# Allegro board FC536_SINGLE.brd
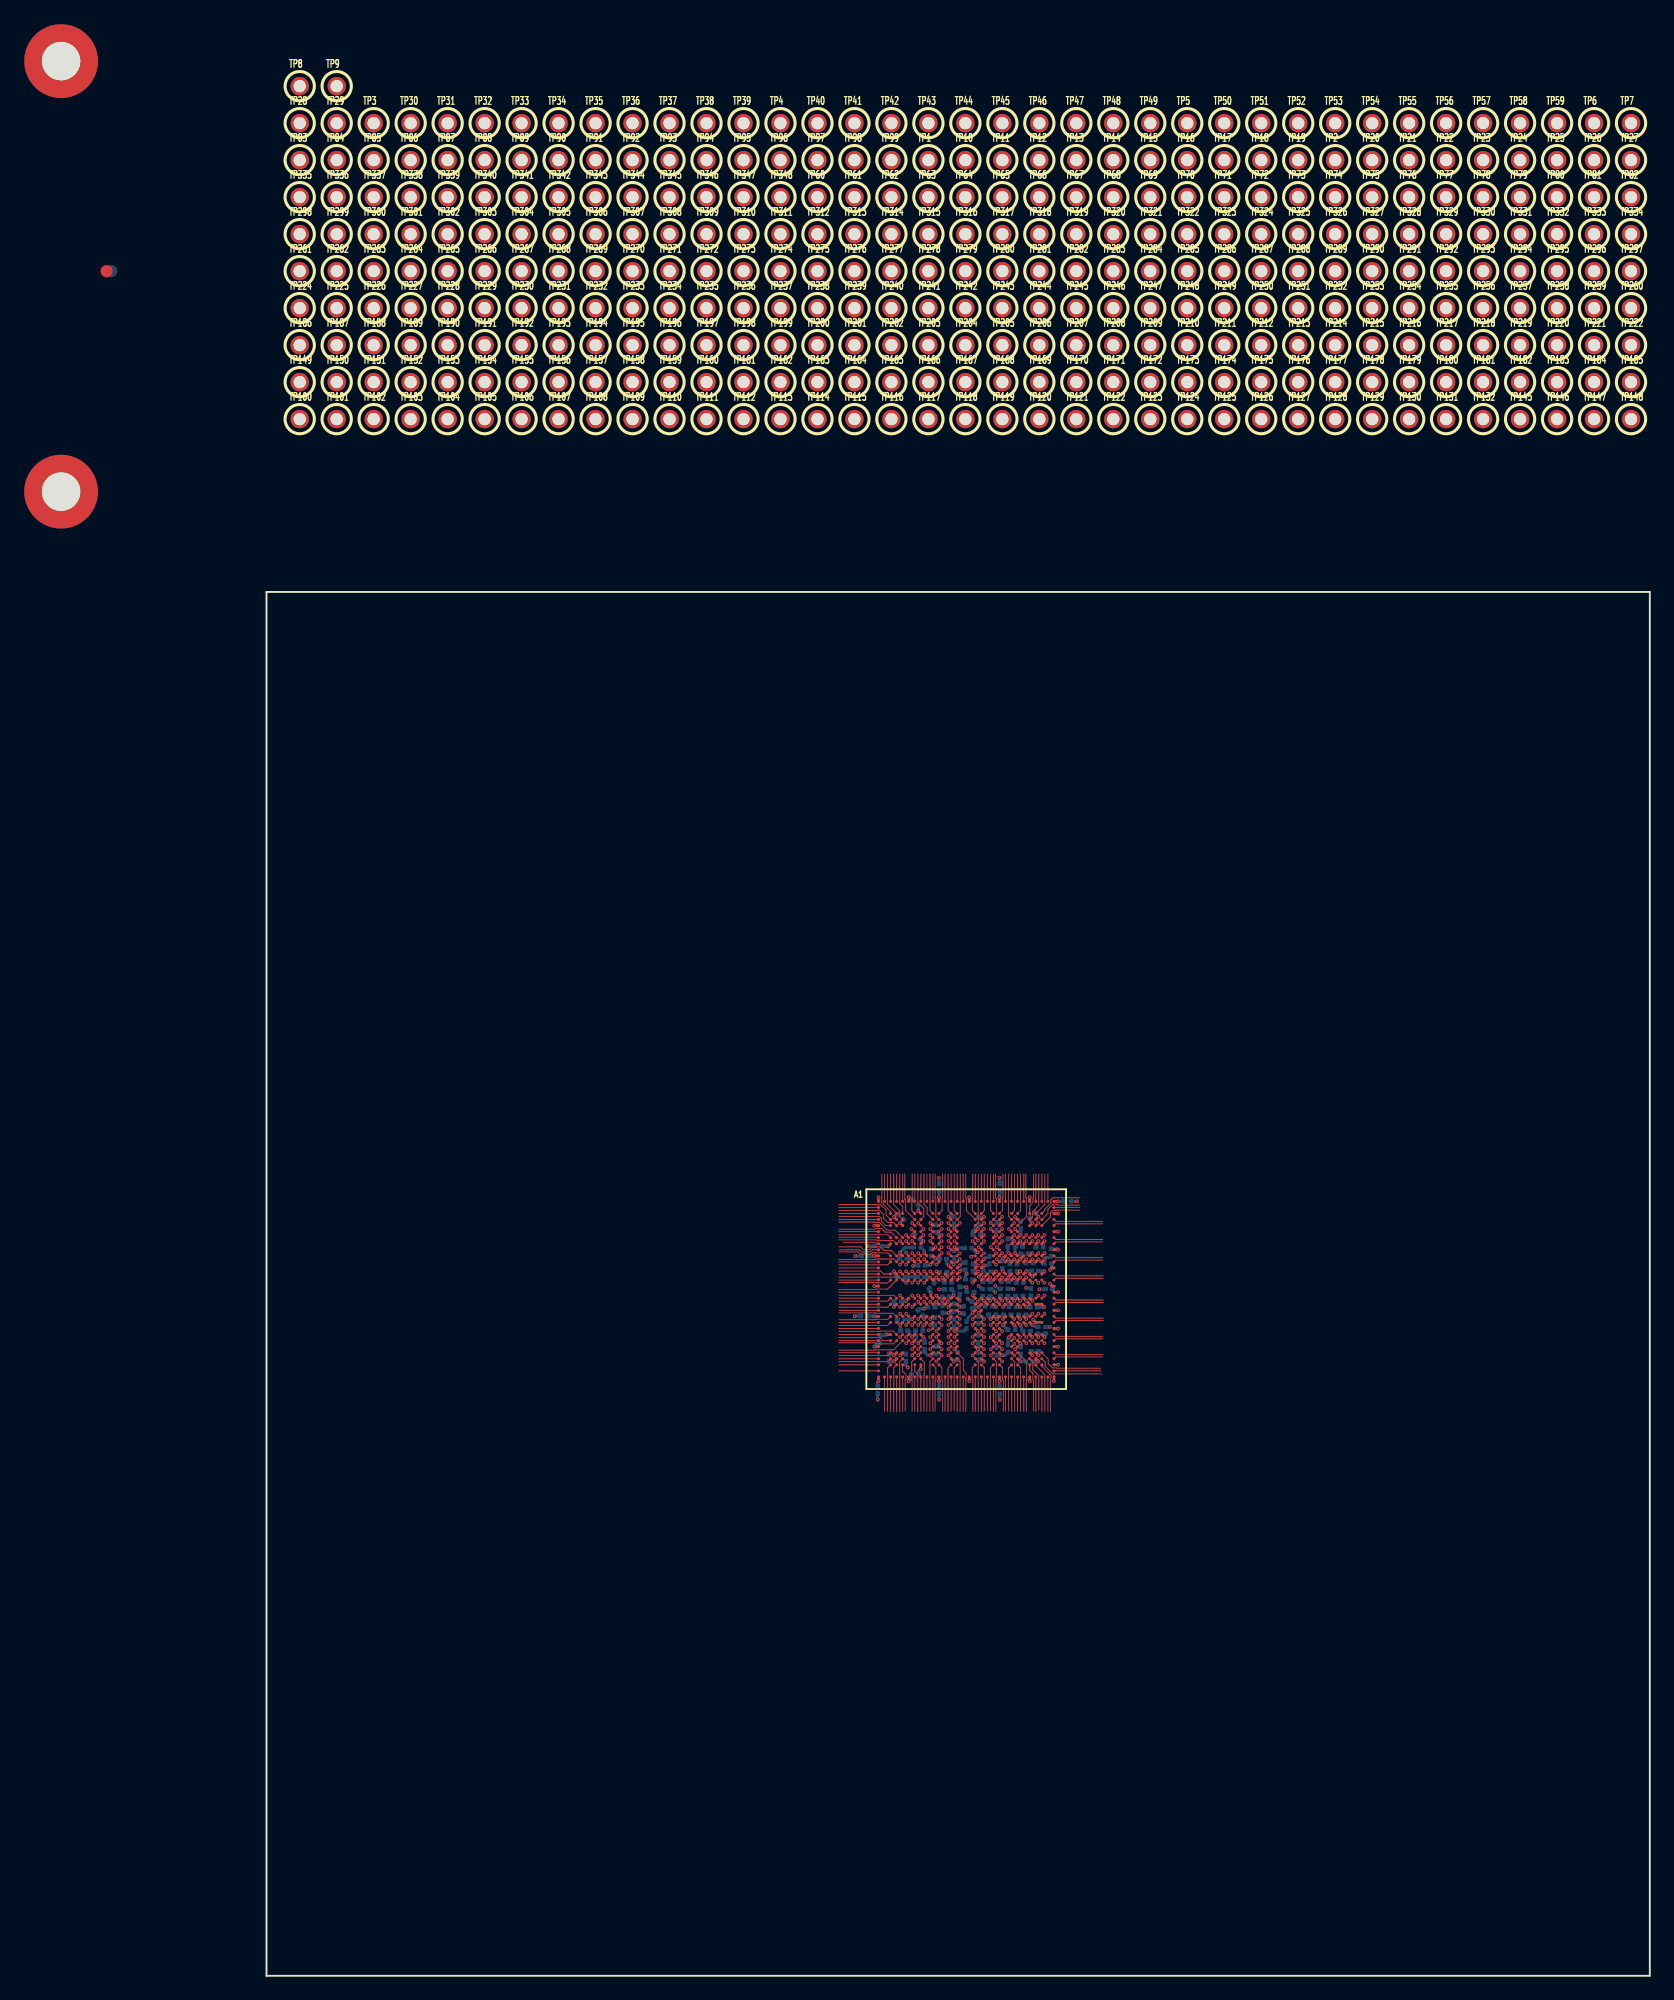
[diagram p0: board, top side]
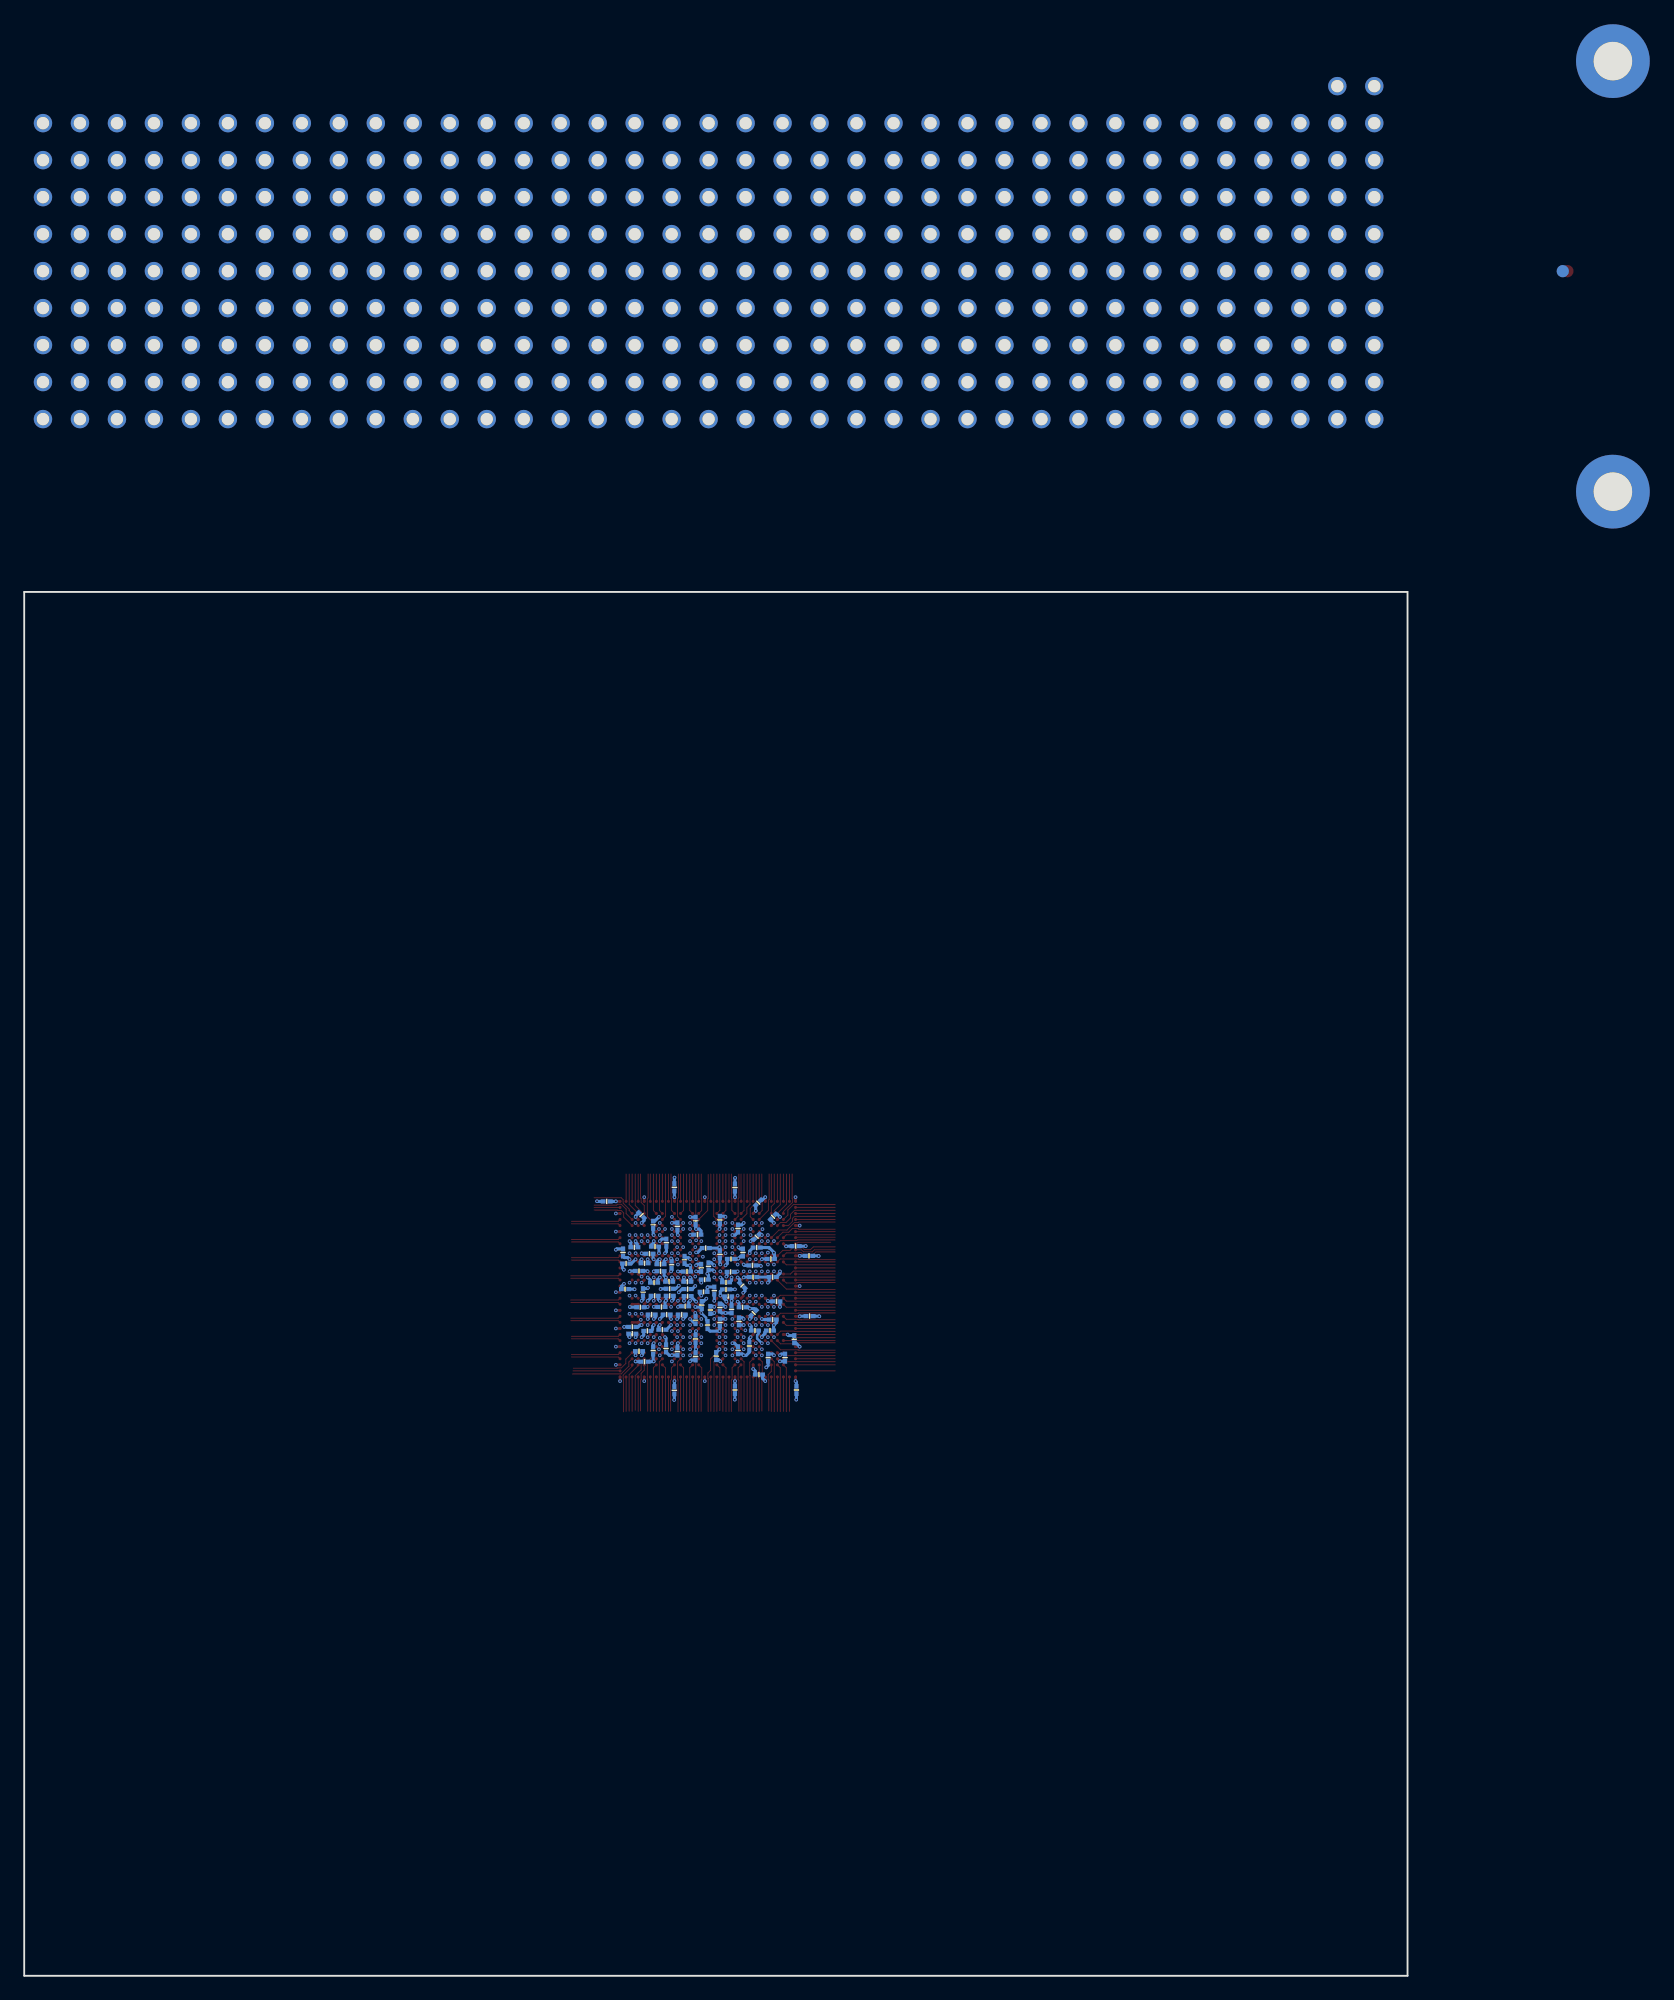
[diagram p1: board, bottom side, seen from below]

Outline 114.3 x 114.3 mm; copper layers: TOP, L2_GND, SIG1, SIG2, L3_PWR, BOTTOM. Coordinates in mm from the lower left corner of the outline.
Outline path: 0,114.3 114.3,114.3 114.3,0 0,0 0,114.3

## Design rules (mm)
net group SERDES_0_INT_REFCLK_: nets SERDES_0_INT_REFCLK_N SERDES_0_INT_REFCLK_P
net group SERDES_0_RX0_: nets SERDES_0_RX0_N SERDES_0_RX0_P
net group SERDES_0_RX1_: nets SERDES_0_RX1_N SERDES_0_RX1_P
net group SERDES_0_RX2_: nets SERDES_0_RX2_N SERDES_0_RX2_P
net group SERDES_0_RX3_: nets SERDES_0_RX3_N SERDES_0_RX3_P
net group SERDES_0_TX0_: nets SERDES_0_TX0_N SERDES_0_TX0_P
net group SERDES_0_TX1_: nets SERDES_0_TX1_N SERDES_0_TX1_P
net group SERDES_0_TX2_: nets SERDES_0_TX2_N SERDES_0_TX2_P
net group SERDES_0_TX3_: nets SERDES_0_TX3_N SERDES_0_TX3_P
net group SERDES_0N_EXT_REFCLK_: nets SERDES_0N_EXT_REFCLK_N SERDES_0N_EXT_REFCLK_P
net group SERDES_0S_EXT_REFCLK_: nets SERDES_0S_EXT_REFCLK_N SERDES_0S_EXT_REFCLK_P

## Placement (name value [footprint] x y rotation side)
C1  0.1UF/10V  [BGA_0201]  56.13 56.11 180 bottom
C2  0.1UF/10V  [BGA_0201]  56.31 56.69 180 bottom
C3  0.1UF/10V  [BGA_0201]  61.01 57.33 180 bottom
C4  0.1UF/10V  [BGA_0201]  58.17 56.49 0 bottom
C5  0.1UF/10V  [BGA_0201]  59.51 57.33 0 bottom
C6  0.1UF/10V  [BGA_0201]  60.96 56.16 180 bottom
C7  0.1UF/10V  [BGA_0201]  59.69 55.3 0 bottom
C8  0.1UF/10V  [BGA_0201]  59.49 56.72 0 bottom
C9  0.1UF/10V  [BGA_0201]  59.49 56.13 0 bottom
C10  0.1UF/10V  [BGA_0201]  57.84 53.75 90 bottom
C11  0.1UF/10V  [BGA_0201]  55.85 55.04 90 bottom
C12  0.1UF/10V  [BGA_0201]  54.94 55.22 0 bottom
C13  0.1UF/10V  [BGA_0201]  56.31 57.28 180 bottom
C14  0.1UF/10V  [BGA_0201]  60.96 56.74 180 bottom
C15  0.1UF/10V  [BGA_0201]  60.81 58.72 270 bottom
C16  0.1UF/10V  [BGA_0201]  58.32 55.4 270 bottom
C17  0.1UF/10V  [BGA_0201]  59.54 58.17 0 bottom
C18  0.1UF/10V  [BGA_0201]  56.82 55.19 90 bottom
C19  0.1UF/10V  [BGA_0201]  61.21 54.61 180 bottom
C20  0.1UF/10V  [BGA_0201]  58.83 54.15 270 bottom
C21  0.1UF/10V  [BGA_0201]  51.44 51.05 90 bottom
C22  0.1UF/10V  [BGA_0201]  54.03 54.74 315 bottom
C23  0.1UF/10V  [BGA_0201]  57.61 54.99 270 bottom
C24  0.1UF/10V  [BGA_0201]  63.5 51.59 0 bottom
C25  0.1UF/10V  [BGA_0201]  59.97 54.61 180 bottom
C26  0.1UF/10V  [BGA_0201]  61.24 60.55 90 bottom
C27  0.1UF/10V  [BGA_0201]  54.91 59.74 90 bottom
C28  0.1UF/10V  [BGA_0201]  57.28 56.59 270 bottom
C29  0.1UF/10V  [BGA_0201]  58.06 57.51 0 bottom
C30  0.1UF/10V  [BGA_0201]  61.26 51.82 90 bottom
C31  0.1UF/10V  [BGA_0201]  54.38 52.02 90 bottom
C32  0.1UF/10V  [BGA_0201]  63.04 58.85 180 bottom
C33  0.1UF/10V  [BGA_0201]  62.46 54.61 0 bottom
C34  0.1UF/10V  [BGA_0201]  62.64 59.64 0 bottom
C35  0.1UF/10V  [BGA_0201]  63.88 60.17 180 bottom
C36  0.1UF/10V  [BGA_0201]  64.06 53.59 180 bottom
C37  0.1UF/10V  [BGA_0201]  63.17 56.46 270 bottom
C38  0.1UF/10V  [BGA_0201]  61.72 58.19 0 bottom
C39  0.1UF/10V  [BGA_0201]  61.65 55.24 0 bottom
C40  0.1UF/10V  [BGA_0201]  64.65 56.72 180 bottom
C41  0.1UF/10V  [BGA_0201]  64.06 53.04 180 bottom
C42  0.1UF/10V  [BGA_0201]  62.81 53.26 180 bottom
C43  0.1UF/10V  [BGA_0201]  62.2 56.16 180 bottom
C44  0.1UF/10V  [BGA_0201]  62.26 57.25 180 bottom
C45  0.1UF/10V  [BGA_0201]  62.18 60.22 180 bottom
C46  0.1UF/10V  [BGA_0201]  58.67 61.21 0 bottom
C47  0.1UF/10V  [BGA_0201]  53.78 61.04 315 bottom
C48  0.1UF/10V  [BGA_0201]  57.76 58.6 90 bottom
C49  0.1UF/10V  [BGA_0201]  56.82 59.59 270 bottom
C50  0.1UF/10V  [BGA_0201]  59.74 59.13 90 bottom
C51  0.1UF/10V  [BGA_0201]  58.37 58.47 90 bottom
C52  0.1UF/10V  [BGA_0201]  54.97 57.01 225 bottom
C53  0.1UF/10V  [BGA_0201]  53.77 60.15 0 bottom
C54  0.1UF/10V  [BGA_0201]  53.92 53.29 0 bottom
C55  0.1UF/10V  [BGA_0201]  55.93 58.14 180 bottom
C56  0.1UF/10V  [BGA_0201]  50.5 48.39 270 bottom
C57  0.1UF/10V  [BGA_0201]  55.58 48.39 270 bottom
C58  0.1UF/10V  [BGA_0201]  52.83 51.05 270 bottom
C59  0.1UF/10V  [BGA_0201]  56.82 53.95 270 bottom
C60  0.1UF/10V  [BGA_0201]  53.59 49.66 180 bottom
C61  0.1UF/10V  [BGA_0201]  55.32 51.66 270 bottom
C62  0.1UF/10V  [BGA_0201]  57.12 51.18 270 bottom
C63  0.1UF/10V  [BGA_0201]  52.68 53.29 180 bottom
C64  0.1UF/10V  [BGA_0201]  55.24 54.05 270 bottom
C65  0.1UF/10V  [BGA_0201]  62.33 51.64 270 bottom
C66  0.1UF/10V  [BGA_0201]  63.04 50.72 180 bottom
C67  0.1UF/10V  [BGA_0201]  60.33 51.56 270 bottom
C68  0.1UF/10V  [BGA_0201]  58.83 52.6 270 bottom
C69  0.1UF/10V  [BGA_0201]  58.83 51.16 90 bottom
C70  0.1UF/10V  [BGA_0201]  60.58 48.36 270 bottom
C71  0.1UF/10V  [BGA_0201]  61.57 53.37 0 bottom
C72  0.1UF/10V  [BGA_0201]  61.72 58.78 0 bottom
C73  0.1UF/10V  [BGA_0201]  58.83 62.36 270 bottom
C74  0.1UF/10V  [BGA_0201]  56.82 62.43 90 bottom
C75  0.1UF/10V  [BGA_0201]  55.32 61.72 90 bottom
C76  0.1UF/10V  [BGA_0201]  66.17 63.96 0 bottom
C77  0.1UF/10V  [BGA_0201]  53.64 63.86 135 bottom
C78  0.1UF/10V  [BGA_0201]  60.58 65.13 90 bottom
C79  0.1UF/10V  [BGA_0201]  55.58 65.1 90 bottom
C80  0.1UF/10V  [BGA_0201]  63.3 62.81 225 bottom
C81  0.1UF/10V  [BGA_0201]  57.99 60.11 180 bottom
C82  0.1UF/10V  [BGA_0201]  60.33 61.9 90 bottom
C83  0.1UF/10V  [BGA_0201]  62.33 62.03 90 bottom
C84  0.1UF/10V  [BGA_0201]  54.13 58.67 180 bottom
C85  0.1UF/10V  [BGA_0201]  55.91 59.21 180 bottom
C86  0.1UF/10V  [BGA_0201]  50.67 52.58 270 bottom
C87  0.1UF/10V  [BGA_0201]  49.4 54.48 180 bottom
C88  0.1UF/10V  [BGA_0201]  52.15 55.7 180 bottom
C89  0.1UF/10V  [BGA_0201]  54.08 57.71 180 bottom
C90  0.1UF/10V  [BGA_0201]  52.45 54.2 180 bottom
C91  0.1UF/10V  [BGA_0201]  52.45 57.71 0 bottom
C92  0.1UF/10V  [BGA_0201]  49.45 59.46 180 bottom
C93  0.1UF/10V  [BGA_0201]  50.56 60.26 180 bottom
C94  0.1UF/10V  [BGA_0201]  52.43 62.69 135 bottom
C95  0.1UF/10V  [BGA_0201]  52.6 59.21 180 bottom
C96  0.1UF/10V  [BGA_0201]  63.5 58.22 0 bottom
C97  0.1UF/10V  [BGA_0201]  63.4 55.22 0 bottom
C98  0.1UF/10V  [BGA_0201]  64.82 59.74 90 bottom
C99  0.1UF/10V  [BGA_0201]  64.57 58.83 0 bottom
NOREF  -  [unnamed]  -16.97 158.14 0 top
NOREF#2  -  [unnamed]  -13.21 140.79 0 top
NOREF#3  -  [#2]  306.73 11.62 0 top
NOREF#4  -  [unnamed]  -16.97 122.58 0 top
NOREF#5  -  [unnamed]  -12.83 140.79 180 bottom
TP1  TP  [TP_40D60]  54.69 149.96 0 top
TP2  TP  [TP_40D60]  88.3 149.96 0 top
TP3  TP  [TP_40D60]  8.86 153.02 0 top
TP4  TP  [TP_40D60]  42.47 153.02 0 top
TP5  TP  [TP_40D60]  76.08 153.02 0 top
TP6  TP  [TP_40D60]  109.69 153.02 0 top
TP7  TP  [TP_40D60]  112.75 153.02 0 top
TP8  TP  [TP_40D60]  2.75 156.07 0 top
TP9  TP  [TP_40D60]  5.8 156.07 0 top
TP10  TP  [TP_40D60]  57.75 149.96 0 top
TP11  TP  [TP_40D60]  60.8 149.96 0 top
TP12  TP  [TP_40D60]  63.86 149.96 0 top
TP13  TP  [TP_40D60]  66.92 149.96 0 top
TP14  TP  [TP_40D60]  69.97 149.96 0 top
TP15  TP  [TP_40D60]  73.03 149.96 0 top
TP16  TP  [TP_40D60]  76.08 149.96 0 top
TP17  TP  [TP_40D60]  79.14 149.96 0 top
TP18  TP  [TP_40D60]  82.19 149.96 0 top
TP19  TP  [TP_40D60]  85.25 149.96 0 top
TP20  TP  [TP_40D60]  91.36 149.96 0 top
TP21  TP  [TP_40D60]  94.42 149.96 0 top
TP22  TP  [TP_40D60]  97.47 149.96 0 top
TP23  TP  [TP_40D60]  100.53 149.96 0 top
TP24  TP  [TP_40D60]  103.58 149.96 0 top
TP25  TP  [TP_40D60]  106.64 149.96 0 top
TP26  TP  [TP_40D60]  109.69 149.96 0 top
TP27  TP  [TP_40D60]  112.75 149.96 0 top
TP28  TP  [TP_40D60]  2.75 153.02 0 top
TP29  TP  [TP_40D60]  5.8 153.02 0 top
TP30  TP  [TP_40D60]  11.91 153.02 0 top
TP31  TP  [TP_40D60]  14.97 153.02 0 top
TP32  TP  [TP_40D60]  18.03 153.02 0 top
TP33  TP  [TP_40D60]  21.08 153.02 0 top
TP34  TP  [TP_40D60]  24.14 153.02 0 top
TP35  TP  [TP_40D60]  27.19 153.02 0 top
TP36  TP  [TP_40D60]  30.25 153.02 0 top
TP37  TP  [TP_40D60]  33.3 153.02 0 top
TP38  TP  [TP_40D60]  36.36 153.02 0 top
TP39  TP  [TP_40D60]  39.41 153.02 0 top
TP40  TP  [TP_40D60]  45.53 153.02 0 top
TP41  TP  [TP_40D60]  48.58 153.02 0 top
TP42  TP  [TP_40D60]  51.64 153.02 0 top
TP43  TP  [TP_40D60]  54.69 153.02 0 top
TP44  TP  [TP_40D60]  57.75 153.02 0 top
TP45  TP  [TP_40D60]  60.8 153.02 0 top
TP46  TP  [TP_40D60]  63.86 153.02 0 top
TP47  TP  [TP_40D60]  66.92 153.02 0 top
TP48  TP  [TP_40D60]  69.97 153.02 0 top
TP49  TP  [TP_40D60]  73.03 153.02 0 top
TP50  TP  [TP_40D60]  79.14 153.02 0 top
TP51  TP  [TP_40D60]  82.19 153.02 0 top
TP52  TP  [TP_40D60]  85.25 153.02 0 top
TP53  TP  [TP_40D60]  88.3 153.02 0 top
TP54  TP  [TP_40D60]  91.36 153.02 0 top
TP55  TP  [TP_40D60]  94.42 153.02 0 top
TP56  TP  [TP_40D60]  97.47 153.02 0 top
TP57  TP  [TP_40D60]  100.53 153.02 0 top
TP58  TP  [TP_40D60]  103.58 153.02 0 top
TP59  TP  [TP_40D60]  106.64 153.02 0 top
TP60  TP  [TP_40D60]  45.53 146.91 0 top
TP61  TP  [TP_40D60]  48.58 146.91 0 top
TP62  TP  [TP_40D60]  51.64 146.91 0 top
TP63  TP  [TP_40D60]  54.69 146.91 0 top
TP64  TP  [TP_40D60]  57.75 146.91 0 top
TP65  TP  [TP_40D60]  60.8 146.91 0 top
TP66  TP  [TP_40D60]  63.86 146.91 0 top
TP67  TP  [TP_40D60]  66.92 146.91 0 top
TP68  TP  [TP_40D60]  69.97 146.91 0 top
TP69  TP  [TP_40D60]  73.03 146.91 0 top
TP70  TP  [TP_40D60]  76.08 146.91 0 top
TP71  TP  [TP_40D60]  79.14 146.91 0 top
TP72  TP  [TP_40D60]  82.19 146.91 0 top
TP73  TP  [TP_40D60]  85.25 146.91 0 top
TP74  TP  [TP_40D60]  88.3 146.91 0 top
TP75  TP  [TP_40D60]  91.36 146.91 0 top
TP76  TP  [TP_40D60]  94.42 146.91 0 top
TP77  TP  [TP_40D60]  97.47 146.91 0 top
TP78  TP  [TP_40D60]  100.53 146.91 0 top
TP79  TP  [TP_40D60]  103.58 146.91 0 top
TP80  TP  [TP_40D60]  106.64 146.91 0 top
TP81  TP  [TP_40D60]  109.69 146.91 0 top
TP82  TP  [TP_40D60]  112.75 146.91 0 top
TP83  TP  [TP_40D60]  2.75 149.96 0 top
TP84  TP  [TP_40D60]  5.8 149.96 0 top
TP85  TP  [TP_40D60]  8.86 149.96 0 top
TP86  TP  [TP_40D60]  11.91 149.96 0 top
TP87  TP  [TP_40D60]  14.97 149.96 0 top
TP88  TP  [TP_40D60]  18.03 149.96 0 top
TP89  TP  [TP_40D60]  21.08 149.96 0 top
TP90  TP  [TP_40D60]  24.14 149.96 0 top
TP91  TP  [TP_40D60]  27.19 149.96 0 top
TP92  TP  [TP_40D60]  30.25 149.96 0 top
TP93  TP  [TP_40D60]  33.3 149.96 0 top
TP94  TP  [TP_40D60]  36.36 149.96 0 top
TP95  TP  [TP_40D60]  39.41 149.96 0 top
TP96  TP  [TP_40D60]  42.47 149.96 0 top
TP97  TP  [TP_40D60]  45.53 149.96 0 top
TP98  TP  [TP_40D60]  48.58 149.96 0 top
TP99  TP  [TP_40D60]  51.64 149.96 0 top
TP100  TP  [TP_40D60]  2.75 128.57 0 top
TP101  TP  [TP_40D60]  5.8 128.57 0 top
TP102  TP  [TP_40D60]  8.86 128.57 0 top
TP103  TP  [TP_40D60]  11.91 128.57 0 top
TP104  TP  [TP_40D60]  14.97 128.57 0 top
TP105  TP  [TP_40D60]  18.03 128.57 0 top
TP106  TP  [TP_40D60]  21.08 128.57 0 top
TP107  TP  [TP_40D60]  24.14 128.57 0 top
TP108  TP  [TP_40D60]  27.19 128.57 0 top
TP109  TP  [TP_40D60]  30.25 128.57 0 top
TP110  TP  [TP_40D60]  33.3 128.57 0 top
TP111  TP  [TP_40D60]  36.36 128.57 0 top
TP112  TP  [TP_40D60]  39.41 128.57 0 top
TP113  TP  [TP_40D60]  42.47 128.57 0 top
TP114  TP  [TP_40D60]  45.53 128.57 0 top
TP115  TP  [TP_40D60]  48.58 128.57 0 top
TP116  TP  [TP_40D60]  51.64 128.57 0 top
TP117  TP  [TP_40D60]  54.69 128.57 0 top
TP118  TP  [TP_40D60]  57.75 128.57 0 top
TP119  TP  [TP_40D60]  60.8 128.57 0 top
TP120  TP  [TP_40D60]  63.86 128.57 0 top
TP121  TP  [TP_40D60]  66.92 128.57 0 top
TP122  TP  [TP_40D60]  69.97 128.57 0 top
TP123  TP  [TP_40D60]  73.03 128.57 0 top
TP124  TP  [TP_40D60]  76.08 128.57 0 top
TP125  TP  [TP_40D60]  79.14 128.57 0 top
TP126  TP  [TP_40D60]  82.19 128.57 0 top
TP127  TP  [TP_40D60]  85.25 128.57 0 top
TP128  TP  [TP_40D60]  88.3 128.57 0 top
TP129  TP  [TP_40D60]  91.36 128.57 0 top
TP130  TP  [TP_40D60]  94.42 128.57 0 top
TP131  TP  [TP_40D60]  97.47 128.57 0 top
TP132  TP  [TP_40D60]  100.53 128.57 0 top
TP145  TP  [TP_40D60]  103.58 128.57 0 top
TP146  TP  [TP_40D60]  106.64 128.57 0 top
TP147  TP  [TP_40D60]  109.69 128.57 0 top
TP148  TP  [TP_40D60]  112.75 128.57 0 top
TP149  TP  [TP_40D60]  2.75 131.63 0 top
TP150  TP  [TP_40D60]  5.8 131.63 0 top
TP151  TP  [TP_40D60]  8.86 131.63 0 top
TP152  TP  [TP_40D60]  11.91 131.63 0 top
TP153  TP  [TP_40D60]  14.97 131.63 0 top
TP154  TP  [TP_40D60]  18.03 131.63 0 top
TP155  TP  [TP_40D60]  21.08 131.63 0 top
TP156  TP  [TP_40D60]  24.14 131.63 0 top
TP157  TP  [TP_40D60]  27.19 131.63 0 top
TP158  TP  [TP_40D60]  30.25 131.63 0 top
TP159  TP  [TP_40D60]  33.3 131.63 0 top
TP160  TP  [TP_40D60]  36.36 131.63 0 top
TP161  TP  [TP_40D60]  39.41 131.63 0 top
TP162  TP  [TP_40D60]  42.47 131.63 0 top
TP163  TP  [TP_40D60]  45.53 131.63 0 top
TP164  TP  [TP_40D60]  48.58 131.63 0 top
TP165  TP  [TP_40D60]  51.64 131.63 0 top
TP166  TP  [TP_40D60]  54.69 131.63 0 top
TP167  TP  [TP_40D60]  57.75 131.63 0 top
TP168  TP  [TP_40D60]  60.8 131.63 0 top
TP169  TP  [TP_40D60]  63.86 131.63 0 top
TP170  TP  [TP_40D60]  66.92 131.63 0 top
TP171  TP  [TP_40D60]  69.97 131.63 0 top
TP172  TP  [TP_40D60]  73.03 131.63 0 top
TP173  TP  [TP_40D60]  76.08 131.63 0 top
TP174  TP  [TP_40D60]  79.14 131.63 0 top
TP175  TP  [TP_40D60]  82.19 131.63 0 top
TP176  TP  [TP_40D60]  85.25 131.63 0 top
TP177  TP  [TP_40D60]  88.3 131.63 0 top
TP178  TP  [TP_40D60]  91.36 131.63 0 top
TP179  TP  [TP_40D60]  94.42 131.63 0 top
TP180  TP  [TP_40D60]  97.47 131.63 0 top
TP181  TP  [TP_40D60]  100.53 131.63 0 top
TP182  TP  [TP_40D60]  103.58 131.63 0 top
TP183  TP  [TP_40D60]  106.64 131.63 0 top
TP184  TP  [TP_40D60]  109.69 131.63 0 top
TP185  TP  [TP_40D60]  112.75 131.63 0 top
TP186  TP  [TP_40D60]  2.75 134.68 0 top
TP187  TP  [TP_40D60]  5.8 134.68 0 top
TP188  TP  [TP_40D60]  8.86 134.68 0 top
TP189  TP  [TP_40D60]  11.91 134.68 0 top
TP190  TP  [TP_40D60]  14.97 134.68 0 top
TP191  TP  [TP_40D60]  18.03 134.68 0 top
TP192  TP  [TP_40D60]  21.08 134.68 0 top
TP193  TP  [TP_40D60]  24.14 134.68 0 top
TP194  TP  [TP_40D60]  27.19 134.68 0 top
TP195  TP  [TP_40D60]  30.25 134.68 0 top
TP196  TP  [TP_40D60]  33.3 134.68 0 top
TP197  TP  [TP_40D60]  36.36 134.68 0 top
TP198  TP  [TP_40D60]  39.41 134.68 0 top
TP199  TP  [TP_40D60]  42.47 134.68 0 top
TP200  TP  [TP_40D60]  45.53 134.68 0 top
TP201  TP  [TP_40D60]  48.58 134.68 0 top
TP202  TP  [TP_40D60]  51.64 134.68 0 top
TP203  TP  [TP_40D60]  54.69 134.68 0 top
TP204  TP  [TP_40D60]  57.75 134.68 0 top
TP205  TP  [TP_40D60]  60.8 134.68 0 top
TP206  TP  [TP_40D60]  63.86 134.68 0 top
TP207  TP  [TP_40D60]  66.92 134.68 0 top
TP208  TP  [TP_40D60]  69.97 134.68 0 top
TP209  TP  [TP_40D60]  73.03 134.68 0 top
TP210  TP  [TP_40D60]  76.08 134.68 0 top
TP211  TP  [TP_40D60]  79.14 134.68 0 top
TP212  TP  [TP_40D60]  82.19 134.68 0 top
TP213  TP  [TP_40D60]  85.25 134.68 0 top
TP214  TP  [TP_40D60]  88.3 134.68 0 top
TP215  TP  [TP_40D60]  91.36 134.68 0 top
TP216  TP  [TP_40D60]  94.42 134.68 0 top
TP217  TP  [TP_40D60]  97.47 134.68 0 top
TP218  TP  [TP_40D60]  100.53 134.68 0 top
TP219  TP  [TP_40D60]  103.58 134.68 0 top
TP220  TP  [TP_40D60]  106.64 134.68 0 top
TP221  TP  [TP_40D60]  109.69 134.68 0 top
TP222  TP  [TP_40D60]  112.75 134.68 0 top
TP224  TP  [TP_40D60]  2.75 137.74 0 top
TP225  TP  [TP_40D60]  5.8 137.74 0 top
TP226  TP  [TP_40D60]  8.86 137.74 0 top
TP227  TP  [TP_40D60]  11.91 137.74 0 top
TP228  TP  [TP_40D60]  14.97 137.74 0 top
TP229  TP  [TP_40D60]  18.03 137.74 0 top
TP230  TP  [TP_40D60]  21.08 137.74 0 top
TP231  TP  [TP_40D60]  24.14 137.74 0 top
TP232  TP  [TP_40D60]  27.19 137.74 0 top
TP233  TP  [TP_40D60]  30.25 137.74 0 top
TP234  TP  [TP_40D60]  33.3 137.74 0 top
TP235  TP  [TP_40D60]  36.36 137.74 0 top
TP236  TP  [TP_40D60]  39.41 137.74 0 top
TP237  TP  [TP_40D60]  42.47 137.74 0 top
TP238  TP  [TP_40D60]  45.53 137.74 0 top
TP239  TP  [TP_40D60]  48.58 137.74 0 top
TP240  TP  [TP_40D60]  51.64 137.74 0 top
TP241  TP  [TP_40D60]  54.69 137.74 0 top
TP242  TP  [TP_40D60]  57.75 137.74 0 top
TP243  TP  [TP_40D60]  60.8 137.74 0 top
TP244  TP  [TP_40D60]  63.86 137.74 0 top
TP245  TP  [TP_40D60]  66.92 137.74 0 top
TP246  TP  [TP_40D60]  69.97 137.74 0 top
TP247  TP  [TP_40D60]  73.03 137.74 0 top
TP248  TP  [TP_40D60]  76.08 137.74 0 top
TP249  TP  [TP_40D60]  79.14 137.74 0 top
TP250  TP  [TP_40D60]  82.19 137.74 0 top
TP251  TP  [TP_40D60]  85.25 137.74 0 top
TP252  TP  [TP_40D60]  88.3 137.74 0 top
TP253  TP  [TP_40D60]  91.36 137.74 0 top
TP254  TP  [TP_40D60]  94.42 137.74 0 top
TP255  TP  [TP_40D60]  97.47 137.74 0 top
TP256  TP  [TP_40D60]  100.53 137.74 0 top
TP257  TP  [TP_40D60]  103.58 137.74 0 top
TP258  TP  [TP_40D60]  106.64 137.74 0 top
TP259  TP  [TP_40D60]  109.69 137.74 0 top
TP260  TP  [TP_40D60]  112.75 137.74 0 top
TP261  TP  [TP_40D60]  2.75 140.8 0 top
TP262  TP  [TP_40D60]  5.8 140.8 0 top
TP263  TP  [TP_40D60]  8.86 140.8 0 top
TP264  TP  [TP_40D60]  11.91 140.8 0 top
TP265  TP  [TP_40D60]  14.97 140.8 0 top
TP266  TP  [TP_40D60]  18.03 140.8 0 top
TP267  TP  [TP_40D60]  21.08 140.8 0 top
TP268  TP  [TP_40D60]  24.14 140.8 0 top
TP269  TP  [TP_40D60]  27.19 140.8 0 top
TP270  TP  [TP_40D60]  30.25 140.8 0 top
TP271  TP  [TP_40D60]  33.3 140.8 0 top
TP272  TP  [TP_40D60]  36.36 140.8 0 top
TP273  TP  [TP_40D60]  39.41 140.8 0 top
TP274  TP  [TP_40D60]  42.47 140.8 0 top
TP275  TP  [TP_40D60]  45.53 140.8 0 top
TP276  TP  [TP_40D60]  48.58 140.8 0 top
TP277  TP  [TP_40D60]  51.64 140.8 0 top
TP278  TP  [TP_40D60]  54.69 140.8 0 top
TP279  TP  [TP_40D60]  57.75 140.8 0 top
TP280  TP  [TP_40D60]  60.8 140.8 0 top
TP281  TP  [TP_40D60]  63.86 140.8 0 top
TP282  TP  [TP_40D60]  66.92 140.8 0 top
TP283  TP  [TP_40D60]  69.97 140.8 0 top
TP284  TP  [TP_40D60]  73.03 140.8 0 top
TP285  TP  [TP_40D60]  76.08 140.8 0 top
TP286  TP  [TP_40D60]  79.14 140.8 0 top
TP287  TP  [TP_40D60]  82.19 140.8 0 top
TP288  TP  [TP_40D60]  85.25 140.8 0 top
TP289  TP  [TP_40D60]  88.3 140.8 0 top
TP290  TP  [TP_40D60]  91.36 140.8 0 top
TP291  TP  [TP_40D60]  94.42 140.8 0 top
TP292  TP  [TP_40D60]  97.47 140.8 0 top
TP293  TP  [TP_40D60]  100.53 140.8 0 top
TP294  TP  [TP_40D60]  103.58 140.8 0 top
TP295  TP  [TP_40D60]  106.64 140.8 0 top
TP296  TP  [TP_40D60]  109.69 140.8 0 top
TP297  TP  [TP_40D60]  112.75 140.8 0 top
TP298  TP  [TP_40D60]  2.75 143.85 0 top
TP299  TP  [TP_40D60]  5.8 143.85 0 top
TP300  TP  [TP_40D60]  8.86 143.85 0 top
TP301  TP  [TP_40D60]  11.91 143.85 0 top
TP302  TP  [TP_40D60]  14.97 143.85 0 top
TP303  TP  [TP_40D60]  18.03 143.85 0 top
TP304  TP  [TP_40D60]  21.08 143.85 0 top
TP305  TP  [TP_40D60]  24.14 143.85 0 top
TP306  TP  [TP_40D60]  27.19 143.85 0 top
TP307  TP  [TP_40D60]  30.25 143.85 0 top
TP308  TP  [TP_40D60]  33.3 143.85 0 top
TP309  TP  [TP_40D60]  36.36 143.85 0 top
TP310  TP  [TP_40D60]  39.41 143.85 0 top
TP311  TP  [TP_40D60]  42.47 143.85 0 top
TP312  TP  [TP_40D60]  45.53 143.85 0 top
TP313  TP  [TP_40D60]  48.58 143.85 0 top
TP314  TP  [TP_40D60]  51.64 143.85 0 top
TP315  TP  [TP_40D60]  54.69 143.85 0 top
TP316  TP  [TP_40D60]  57.75 143.85 0 top
TP317  TP  [TP_40D60]  60.8 143.85 0 top
TP318  TP  [TP_40D60]  63.86 143.85 0 top
TP319  TP  [TP_40D60]  66.92 143.85 0 top
TP320  TP  [TP_40D60]  69.97 143.85 0 top
TP321  TP  [TP_40D60]  73.03 143.85 0 top
TP322  TP  [TP_40D60]  76.08 143.85 0 top
TP323  TP  [TP_40D60]  79.14 143.85 0 top
TP324  TP  [TP_40D60]  82.19 143.85 0 top
TP325  TP  [TP_40D60]  85.25 143.85 0 top
TP326  TP  [TP_40D60]  88.3 143.85 0 top
TP327  TP  [TP_40D60]  91.36 143.85 0 top
TP328  TP  [TP_40D60]  94.42 143.85 0 top
TP329  TP  [TP_40D60]  97.47 143.85 0 top
TP330  TP  [TP_40D60]  100.53 143.85 0 top
TP331  TP  [TP_40D60]  103.58 143.85 0 top
TP332  TP  [TP_40D60]  106.64 143.85 0 top
TP333  TP  [TP_40D60]  109.69 143.85 0 top
TP334  TP  [TP_40D60]  112.75 143.85 0 top
TP335  TP  [TP_40D60]  2.75 146.91 0 top
TP336  TP  [TP_40D60]  5.8 146.91 0 top
TP337  TP  [TP_40D60]  8.86 146.91 0 top
TP338  TP  [TP_40D60]  11.91 146.91 0 top
TP339  TP  [TP_40D60]  14.97 146.91 0 top
TP340  TP  [TP_40D60]  18.03 146.91 0 top
TP341  TP  [TP_40D60]  21.08 146.91 0 top
TP342  TP  [TP_40D60]  24.14 146.91 0 top
TP343  TP  [TP_40D60]  27.19 146.91 0 top
TP344  TP  [TP_40D60]  30.25 146.91 0 top
TP345  TP  [TP_40D60]  33.3 146.91 0 top
TP346  TP  [TP_40D60]  36.36 146.91 0 top
TP347  TP  [TP_40D60]  39.41 146.91 0 top
TP348  TP  [TP_40D60]  42.47 146.91 0 top
U1  -  [M5P300-FCS536]  57.82 56.71 0 top

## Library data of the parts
C1-C99 = CAPACITOR NON-POL
TP1-TP132 TP145-TP222 TP224-TP348 = T POINT A
U1 = M5P300-FCS536_Pin

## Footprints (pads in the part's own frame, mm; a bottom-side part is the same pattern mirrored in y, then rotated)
BGA_0201
  rect 0.4x0.35 smd: 1(-0.3,0) 2(0.3,0)
M5P300-FCS536
  round 0.254 smd: A1(-7.25,7.25) A2(-6.75,7.25) A3(-6.25,7.25) A4(-5.75,7.25) A5(-5.25,7.25) A6(-4.75,7.25) A7(-4.25,7.25) A8(-3.75,7.25) A9(-3.25,7.25) A10(-2.75,7.25) A11(-2.25,7.25) A12(-1.75,7.25) A13(-1.25,7.25) A14(-0.75,7.25) A15(-0.25,7.25) A16(0.25,7.25) A17(0.75,7.25) A18(1.25,7.25) A19(1.75,7.25) A20(2.25,7.25) A21(2.75,7.25) A22(3.25,7.25) A23(3.75,7.25) A24(4.25,7.25) A25(4.75,7.25) A26(5.25,7.25) A27(5.75,7.25) A28(6.25,7.25) A29(6.75,7.25) A30(7.25,7.25) AA1(-7.25,-2.75) AA3(-6.25,-2.75) AA4(-5.75,-2.75) AA5(-5.25,-2.75) AA6(-4.75,-2.75) AA7(-4.25,-2.75) AA8(-3.75,-2.75) AA9(-3.25,-2.75) AA10(-2.75,-2.75) AA11(-2.25,-2.75) AA13(-1.25,-2.75) AA14(-0.75,-2.75) AA17(0.75,-2.75) AA18(1.25,-2.75) AA20(2.25,-2.75) AA21(2.75,-2.75) AA22(3.25,-2.75) AA23(3.75,-2.75) AA24(4.25,-2.75) AA25(4.75,-2.75) AA26(5.25,-2.75) AA27(5.75,-2.75) AA28(6.25,-2.75) AA30(7.25,-2.75) AB1(-7.25,-3.25) AB10(-2.75,-3.25) AB11(-2.25,-3.25) AB13(-1.25,-3.25) AB14(-0.75,-3.25) AB17(0.75,-3.25) AB18(1.25,-3.25) AB20(2.25,-3.25) AB21(2.75,-3.25) AB30(7.25,-3.25) AC1(-7.25,-3.75) AC3(-6.25,-3.75) AC4(-5.75,-3.75) AC5(-5.25,-3.75) AC6(-4.75,-3.75) AC7(-4.25,-3.75) AC8(-3.75,-3.75) AC10(-2.75,-3.75) AC11(-2.25,-3.75) AC13(-1.25,-3.75) AC14(-0.75,-3.75) AC17(0.75,-3.75) AC18(1.25,-3.75) AC20(2.25,-3.75) AC21(2.75,-3.75) AC23(3.75,-3.75) AC24(4.25,-3.75) AC25(4.75,-3.75) AC26(5.25,-3.75) AC27(5.75,-3.75) AC28(6.25,-3.75) AC30(7.25,-3.75) AD1(-7.25,-4.25) AD3(-6.25,-4.25) AD4(-5.75,-4.25) AD5(-5.25,-4.25) AD6(-4.75,-4.25) AD7(-4.25,-4.25) AD8(-3.75,-4.25) AD10(-2.75,-4.25) AD11(-2.25,-4.25) AD13(-1.25,-4.25) AD14(-0.75,-4.25) AD17(0.75,-4.25) AD18(1.25,-4.25) AD20(2.25,-4.25) AD21(2.75,-4.25) AD23(3.75,-4.25) AD24(4.25,-4.25) AD25(4.75,-4.25) AD26(5.25,-4.25) AD27(5.75,-4.25) AD28(6.25,-4.25) AD30(7.25,-4.25) AE1(-7.25,-4.75) AE7(-4.25,-4.75) AE8(-3.75,-4.75) AE10(-2.75,-4.75) AE11(-2.25,-4.75) AE13(-1.25,-4.75) AE14(-0.75,-4.75) AE17(0.75,-4.75) AE18(1.25,-4.75) AE20(2.25,-4.75) AE21(2.75,-4.75) AE23(3.75,-4.75) AE24(4.25,-4.75) AE30(7.25,-4.75) AF1(-7.25,-5.25) AF3(-6.25,-5.25) AF4(-5.75,-5.25) AF5(-5.25,-5.25) AF7(-4.25,-5.25) AF8(-3.75,-5.25) AF10(-2.75,-5.25) AF11(-2.25,-5.25) AF13(-1.25,-5.25) AF14(-0.75,-5.25) AF17(0.75,-5.25) AF18(1.25,-5.25) AF20(2.25,-5.25) AF21(2.75,-5.25) AF23(3.75,-5.25) AF24(4.25,-5.25) AF26(5.25,-5.25) AF27(5.75,-5.25) AF28(6.25,-5.25) AF30(7.25,-5.25) AG1(-7.25,-5.75) AG3(-6.25,-5.75) AG4(-5.75,-5.75) AG5(-5.25,-5.75) AG7(-4.25,-5.75) AG8(-3.75,-5.75) AG10(-2.75,-5.75) AG11(-2.25,-5.75) AG13(-1.25,-5.75) AG14(-0.75,-5.75) AG17(0.75,-5.75) AG18(1.25,-5.75) AG20(2.25,-5.75) AG21(2.75,-5.75) AG23(3.75,-5.75) AG24(4.25,-5.75) AG26(5.25,-5.75) AG27(5.75,-5.75) AG28(6.25,-5.75) AG30(7.25,-5.75) AH1(-7.25,-6.25) AH3(-6.25,-6.25) AH4(-5.75,-6.25) AH5(-5.25,-6.25) AH7(-4.25,-6.25) AH8(-3.75,-6.25) AH10(-2.75,-6.25) AH11(-2.25,-6.25) AH13(-1.25,-6.25) AH14(-0.75,-6.25) AH17(0.75,-6.25) AH18(1.25,-6.25) AH20(2.25,-6.25) AH21(2.75,-6.25) AH23(3.75,-6.25) AH24(4.25,-6.25) AH26(5.25,-6.25) AH27(5.75,-6.25) AH28(6.25,-6.25) AH30(7.25,-6.25) AJ1(-7.25,-6.75) AJ30(7.25,-6.75) AK1(-7.25,-7.25) AK2(-6.75,-7.25) AK3(-6.25,-7.25) AK4(-5.75,-7.25) AK5(-5.25,-7.25) AK6(-4.75,-7.25) AK7(-4.25,-7.25) AK8(-3.75,-7.25) AK9(-3.25,-7.25) AK10(-2.75,-7.25) AK11(-2.25,-7.25) AK12(-1.75,-7.25) AK13(-1.25,-7.25) AK14(-0.75,-7.25) AK15(-0.25,-7.25) AK16(0.25,-7.25) AK17(0.75,-7.25) AK18(1.25,-7.25) AK19(1.75,-7.25) AK20(2.25,-7.25) AK21(2.75,-7.25) AK22(3.25,-7.25) AK23(3.75,-7.25) AK24(4.25,-7.25) AK25(4.75,-7.25) AK26(5.25,-7.25) AK27(5.75,-7.25) AK28(6.25,-7.25) AK29(6.75,-7.25) AK30(7.25,-7.25) B1(-7.25,6.75) B30(7.25,6.75) C1(-7.25,6.25) C3(-6.25,6.25) C4(-5.75,6.25) C5(-5.25,6.25) C7(-4.25,6.25) C8(-3.75,6.25) C10(-2.75,6.25) C11(-2.25,6.25) C13(-1.25,6.25) C14(-0.75,6.25) C17(0.75,6.25) C18(1.25,6.25) C20(2.25,6.25) C21(2.75,6.25) C23(3.75,6.25) C24(4.25,6.25) C26(5.25,6.25) C27(5.75,6.25) C28(6.25,6.25) C30(7.25,6.25) D1(-7.25,5.75) D3(-6.25,5.75) D4(-5.75,5.75) D5(-5.25,5.75) D7(-4.25,5.75) D8(-3.75,5.75) D10(-2.75,5.75) D11(-2.25,5.75) D13(-1.25,5.75) D14(-0.75,5.75) D17(0.75,5.75) D18(1.25,5.75) D20(2.25,5.75) D21(2.75,5.75) D23(3.75,5.75) D24(4.25,5.75) D26(5.25,5.75) D27(5.75,5.75) D28(6.25,5.75) D30(7.25,5.75) E1(-7.25,5.25) E3(-6.25,5.25) E4(-5.75,5.25) E5(-5.25,5.25) E7(-4.25,5.25) E8(-3.75,5.25) E10(-2.75,5.25) E11(-2.25,5.25) E13(-1.25,5.25) E14(-0.75,5.25) E17(0.75,5.25) E18(1.25,5.25) E20(2.25,5.25) E21(2.75,5.25) E23(3.75,5.25) E24(4.25,5.25) E26(5.25,5.25) E27(5.75,5.25) E28(6.25,5.25) E30(7.25,5.25) F1(-7.25,4.75) F7(-4.25,4.75) F8(-3.75,4.75) F10(-2.75,4.75) F11(-2.25,4.75) F13(-1.25,4.75) F14(-0.75,4.75) F17(0.75,4.75) F18(1.25,4.75) F20(2.25,4.75) F21(2.75,4.75) F23(3.75,4.75) F24(4.25,4.75) F30(7.25,4.75) G1(-7.25,4.25) G3(-6.25,4.25) G4(-5.75,4.25) G5(-5.25,4.25) G6(-4.75,4.25) G7(-4.25,4.25) G8(-3.75,4.25) G10(-2.75,4.25) G11(-2.25,4.25) G13(-1.25,4.25) G14(-0.75,4.25) G17(0.75,4.25) G18(1.25,4.25) G20(2.25,4.25) G21(2.75,4.25) G23(3.75,4.25) G24(4.25,4.25) G25(4.75,4.25) G26(5.25,4.25) G27(5.75,4.25) G28(6.25,4.25) G30(7.25,4.25) H1(-7.25,3.75) H3(-6.25,3.75) H4(-5.75,3.75) H5(-5.25,3.75) H6(-4.75,3.75) H7(-4.25,3.75) H8(-3.75,3.75) H10(-2.75,3.75) H11(-2.25,3.75) H13(-1.25,3.75) H14(-0.75,3.75) H17(0.75,3.75) H18(1.25,3.75) H20(2.25,3.75) H21(2.75,3.75) H23(3.75,3.75) H24(4.25,3.75) H25(4.75,3.75) H26(5.25,3.75) H27(5.75,3.75) H28(6.25,3.75) H30(7.25,3.75) J1(-7.25,3.25) J10(-2.75,3.25) J11(-2.25,3.25) J13(-1.25,3.25) J14(-0.75,3.25) J17(0.75,3.25) J18(1.25,3.25) J20(2.25,3.25) J21(2.75,3.25) J30(7.25,3.25) K1(-7.25,2.75) K3(-6.25,2.75) K4(-5.75,2.75) K5(-5.25,2.75) K6(-4.75,2.75) K7(-4.25,2.75) K8(-3.75,2.75) K9(-3.25,2.75) K10(-2.75,2.75) K11(-2.25,2.75) K13(-1.25,2.75) K14(-0.75,2.75) K17(0.75,2.75) K18(1.25,2.75) K20(2.25,2.75) K21(2.75,2.75) K22(3.25,2.75) K23(3.75,2.75) K24(4.25,2.75) K25(4.75,2.75) K26(5.25,2.75) K27(5.75,2.75) K28(6.25,2.75) K30(7.25,2.75) L1(-7.25,2.25) L3(-6.25,2.25) L4(-5.75,2.25) L5(-5.25,2.25) L6(-4.75,2.25) L7(-4.25,2.25) L8(-3.75,2.25) L9(-3.25,2.25) L10(-2.75,2.25) L11(-2.25,2.25) L13(-1.25,2.25) L14(-0.75,2.25) L17(0.75,2.25) L18(1.25,2.25) L20(2.25,2.25) L21(2.75,2.25) L22(3.25,2.25) L23(3.75,2.25) L24(4.25,2.25) L25(4.75,2.25) L26(5.25,2.25) L27(5.75,2.25) L28(6.25,2.25) L30(7.25,2.25) M1(-7.25,1.75) M13(-1.25,1.75) M14(-0.75,1.75) M17(0.75,1.75) M18(1.25,1.75) M30(7.25,1.75) N1(-7.25,1.25) N3(-6.25,1.25) N4(-5.75,1.25) N5(-5.25,1.25) N6(-4.75,1.25) N7(-4.25,1.25) N8(-3.75,1.25) N9(-3.25,1.25) N10(-2.75,1.25) N11(-2.25,1.25) N12(-1.75,1.25) N13(-1.25,1.25) N14(-0.75,1.25) N17(0.75,1.25) N18(1.25,1.25) N19(1.75,1.25) N20(2.25,1.25) N21(2.75,1.25) N22(3.25,1.25) N23(3.75,1.25) N24(4.25,1.25) N25(4.75,1.25) N26(5.25,1.25) N27(5.75,1.25) N28(6.25,1.25) N30(7.25,1.25) P1(-7.25,0.75) P3(-6.25,0.75) P4(-5.75,0.75) P5(-5.25,0.75) P6(-4.75,0.75) P7(-4.25,0.75) P8(-3.75,0.75) P9(-3.25,0.75) P10(-2.75,0.75) P11(-2.25,0.75) P12(-1.75,0.75) P13(-1.25,0.75) P14(-0.75,0.75) P17(0.75,0.75) P18(1.25,0.75) P19(1.75,0.75) P20(2.25,0.75) P21(2.75,0.75) P22(3.25,0.75) P23(3.75,0.75) P24(4.25,0.75) P25(4.75,0.75) P26(5.25,0.75) P27(5.75,0.75) P28(6.25,0.75) P30(7.25,0.75) R1(-7.25,0.25) R30(7.25,0.25) T1(-7.25,-0.25) T30(7.25,-0.25) U1(-7.25,-0.75) U3(-6.25,-0.75) U4(-5.75,-0.75) U5(-5.25,-0.75) U6(-4.75,-0.75) U7(-4.25,-0.75) U8(-3.75,-0.75) U9(-3.25,-0.75) U10(-2.75,-0.75) U11(-2.25,-0.75) U12(-1.75,-0.75) U13(-1.25,-0.75) U14(-0.75,-0.75) U17(0.75,-0.75) U18(1.25,-0.75) U19(1.75,-0.75) U20(2.25,-0.75) U21(2.75,-0.75) U22(3.25,-0.75) U23(3.75,-0.75) U24(4.25,-0.75) U25(4.75,-0.75) U26(5.25,-0.75) U27(5.75,-0.75) U28(6.25,-0.75) U30(7.25,-0.75) V1(-7.25,-1.25) V3(-6.25,-1.25) V4(-5.75,-1.25) V5(-5.25,-1.25) V6(-4.75,-1.25) V7(-4.25,-1.25) V8(-3.75,-1.25) V9(-3.25,-1.25) V10(-2.75,-1.25) V11(-2.25,-1.25) V12(-1.75,-1.25) V13(-1.25,-1.25) V14(-0.75,-1.25) V17(0.75,-1.25) V18(1.25,-1.25) V19(1.75,-1.25) V20(2.25,-1.25) V21(2.75,-1.25) V22(3.25,-1.25) V23(3.75,-1.25) V24(4.25,-1.25) V25(4.75,-1.25) V26(5.25,-1.25) V27(5.75,-1.25) V28(6.25,-1.25) V30(7.25,-1.25) W1(-7.25,-1.75) W13(-1.25,-1.75) W14(-0.75,-1.75) W17(0.75,-1.75) W18(1.25,-1.75) W30(7.25,-1.75) Y1(-7.25,-2.25) Y3(-6.25,-2.25) Y4(-5.75,-2.25) Y5(-5.25,-2.25) Y6(-4.75,-2.25) Y7(-4.25,-2.25) Y8(-3.75,-2.25) Y9(-3.25,-2.25) Y10(-2.75,-2.25) Y11(-2.25,-2.25) Y13(-1.25,-2.25) Y14(-0.75,-2.25) Y17(0.75,-2.25) Y18(1.25,-2.25) Y20(2.25,-2.25) Y21(2.75,-2.25) Y22(3.25,-2.25) Y23(3.75,-2.25) Y24(4.25,-2.25) Y25(4.75,-2.25) Y26(5.25,-2.25) Y27(5.75,-2.25) Y28(6.25,-2.25) Y30(7.25,-2.25)
TP_40D60
  round 1.524 hole 1.016: 1(0,0)
unnamed
  round 6.096 hole 3.175 unplated: (0,0)

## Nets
GND: C1.1 C2.1 C3.1 C4.1 C5.1 C6.1 C7.1 C8.1 C9.1 C10.1 C11.1 C12.1 C13.1 C14.1 C15.1 C16.1 C17.1 C18.1 C19.1 C20.1 C21.1 C22.1 C23.1 C24.1 C25.1 C26.1 C27.1 C28.1 C29.1 C30.1 C31.1 C32.1 C33.1 C34.1 C35.1 C36.1 C37.1 C38.1 C39.1 C40.1 C41.1 C42.1 C43.1 C44.1 C45.1 C46.1 C47.1 C48.1 C49.1 C50.1 C51.1 C52.1 C53.1 C54.1 C55.1 C56.2 C57.2 C58.2 C59.2 C60.2 C61.2 C62.2 C63.2 C64.2 C65.2 C66.2 C67.2 C68.2 C69.2 C70.2 C71.2 C72.2 C73.2 C74.2 C75.2 C76.2 C77.2 C78.2 C79.2 C80.2 C81.2 C82.2 C83.2 C84.2 C85.2 C86.2 C87.2 C88.2 C89.2 C90.2 C91.2 C92.2 C93.2 C94.2 C95.2 C96.2 C97.2 C98.2 C99.2 U1.A1(VSS_1) U1.A6(VSS_4) U1.A16(VSS_2) U1.A26(VSS_3) U1.AA5(VSS_6) U1.AA10(VSS_5) U1.AA23(VSSA_1) U1.AA25(VSSA_2) U1.AA27(VSSA_3) U1.AA28(VSSA_4) U1.AB14(VSS_7) U1.AB30(VSSA_5) U1.AC24(VSS_8) U1.AC26(VSSA_6) U1.AC28(VSSA_7) U1.AD7(VSS_9) U1.AE1(VSS_10) U1.AE17(VSS_11) U1.AE30(VSSA_8) U1.AF10(VSS_12) U1.AF21(VSS_13) U1.AF26(VSS_14) U1.AG4(VSS_17) U1.AG13(VSS_15) U1.AG24(VSS_16) U1.AH30(VSSA_9) U1.AK6(VSS_21) U1.AK16(VSS_18) U1.AK26(VSS_19) U1.AK30(VSS_20) U1.C30(VSSA_10) U1.D4(VSS_24) U1.D13(VSS_22) U1.D24(VSS_23) U1.E1(VSS_25) U1.E10(VSS_26) U1.E21(VSS_27) U1.E26(VSS_28) U1.F17(VSS_29) U1.F30(VSSA_11) U1.G7(VSS_30) U1.H24(VSS_31) U1.H26(VSSA_12) U1.H28(VSSA_13) U1.J14(VSS_32) U1.J30(VSSA_14) U1.K5(VSS_35) U1.K10(VSS_33) U1.K22(VSS_34) U1.K23(VSSA_15) U1.K25(VSSA_16) U1.K27(VSSA_17) U1.K28(VSSA_18) U1.L23(VSSA_19) U1.L24(VSSA_20) U1.L26(VSSA_21) U1.M18(VSS_36) U1.M30(VSSA_22) U1.N12(VSS_37) U1.N14(VSS_38) U1.N17(VSS_39) U1.N19(VSS_40) U1.N21(VSS_41) U1.N23(VSSA_23) U1.N26(VSSA_24) U1.N27(VSSA_25) U1.N28(VSSA_26) U1.P6(VSS_47) U1.P11(VSS_42) U1.P13(VSS_43) U1.P18(VSS_44) U1.P20(VSS_45) U1.P22(VSS_46) U1.P24(VSSA_27) U1.P25(VSSA_28) U1.R1(VSS_48) U1.R30(VSSA_29) U1.T30(VSSA_30) U1.U11(VSS_49) U1.U13(VSS_50) U1.U18(VSS_51) U1.U20(VSS_52) U1.U22(VSS_53) U1.U24(VSSA_31) U1.U25(VSSA_32) U1.V4(VSS_59) U1.V12(VSS_54) U1.V14(VSS_55) U1.V17(VSS_56) U1.V19(VSS_57) U1.V21(VSS_58) U1.V23(VSSA_33) U1.V26(VSSA_34) U1.V27(VSSA_35) U1.V28(VSSA_36) U1.W13(VSS_60) U1.W18(VSS_61) U1.W30(VSSA_37) U1.Y21(VSS_62) U1.Y23(VSSA_38) U1.Y24(VSSA_39) U1.Y26(VSSA_40)
VDD: C1.2 C2.2 C3.2 C4.2 C5.2 C6.2 C7.2 C8.2 C9.2 C10.2 C11.2 C12.2 C13.2 C14.2 C15.2 C16.2 C17.2 C18.2 U1.N13(VDD_1) U1.N18(VDD_2) U1.N20(VDD_3) U1.N22(VDD_4) U1.P12(VDD_5) U1.P14(VDD_6) U1.P19(VDD_7) U1.P21(VDD_8) U1.U12(VDD_9) U1.U17(VDD_10) U1.U19(VDD_11) U1.U21(VDD_12) U1.V11(VDD_13) U1.V13(VDD_14) U1.V18(VDD_15) U1.V20(VDD_16) U1.V22(VDD_17) U1.W17(VDD_18)
VDD18: C19.2 C20.2 C21.2 C22.2 C23.2 C24.2 C25.2 U1.AF4(VDD18_2) U1.AF27(VDD18_1) U1.W14(VDD18_3) U1.Y9(VDD18_7) U1.Y18(VDD18_4) U1.Y20(VDD18_5) U1.Y22(VDD18_6)
VDD25: C26.2 C27.2 C28.2 C29.2 C30.2 C31.2 U1.AC8(VDD25_2) U1.AC23(VDD25_1) U1.H23(VDD25_3) U1.J10(VDD25_4) U1.P17(VDD25_5) U1.U14(VDD25_6)
VDDA: C32.2 C33.2 C34.2 C35.2 C36.2 C37.2 C38.2 C39.2 C40.2 C41.2 U1.AA26(VDDA_1) U1.AC27(VDDA_2) U1.H27(VDDA_3) U1.K26(VDDA_4) U1.L25(VDDA_5) U1.N24(VDDA_6) U1.P26(VDDA_7) U1.U26(VDDA_8) U1.V24(VDDA_9) U1.Y25(VDDA_10)
VDDA25: C42.2 C43.2 C44.2 C45.2 U1.AA24(VDDA25_1) U1.K24(VDDA25_2) U1.P23(VDDA25_3) U1.U23(VDDA25_4)
VDDAUX2: C46.2 C47.2 C48.2 C49.2 C50.2 C51.2 U1.G18(VDDAUX2_1) U1.H8(VDDAUX2_2) U1.L13(VDDAUX2_3) U1.L18(VDDAUX2_4) U1.M14(VDDAUX2_5) U1.M17(VDDAUX2_6)
VDDAUX4: C52.2 C53.2 C54.2 C55.2 U1.AA9(VDDAUX4_1) U1.K9(VDDAUX4_2) U1.N11(VDDAUX4_3) U1.U10(VDDAUX4_4)
VDDI0: C56.1 C57.1 C58.1 C59.1 C60.1 C61.1 C62.1 C63.1 C64.1 U1.AC7(VDDI0_1) U1.AD11(VDDI0_2) U1.AE14(VDDI0_3) U1.AF5(VDDI0_4) U1.AH8(VDDI0_5) U1.AK1(VDDI0_6) U1.AK11(VDDI0_7) U1.Y10(VDDI0_8) U1.Y13(VDDI0_9)
VDDI1: C65.1 C66.1 C67.1 C68.1 C69.1 C70.1 C71.1 U1.AA22(VDDI1_1) U1.AB17(VDDI1_2) U1.AD20(VDDI1_3) U1.AD24(VDDI1_4) U1.AG18(VDDI1_5) U1.AG27(VDDI1_6) U1.AK21(VDDI1_7)
VDDI2: C72.1 C73.1 C74.1 C75.1 C76.1 C77.1 C78.1 C79.1 C80.1 C81.1 C82.1 C83.1 U1.A11(VDDI2_1) U1.A21(VDDI2_2) U1.A30(VDDI2_3) U1.C8(VDDI2_4) U1.D18(VDDI2_5) U1.D27(VDDI2_6) U1.F14(VDDI2_7) U1.G11(VDDI2_8) U1.G20(VDDI2_9) U1.G24(VDDI2_10) U1.J17(VDDI2_11) U1.L22(VDDI2_12)
VDDI3: C84.1 C85.1 U1.L10(VDDI3_1) U1.M13(VDDI3_2)
VDDI4: C86.1 C87.1 C88.1 C89.1 C90.1 C91.1 C92.1 C93.1 C94.1 C95.1 U1.AC3(VDDI4_1) U1.E5(VDDI4_2) U1.H3(VDDI4_3) U1.K1(VDDI4_4) U1.L7(VDDI4_5) U1.N4(VDDI4_6) U1.P10(VDDI4_7) U1.U6(VDDI4_8) U1.Y1(VDDI4_9) U1.Y7(VDDI4_10)
VDDSREF: C96.1 C97.1 U1.N25(VDDSREF_1) U1.V25(VDDSREF_2)
DEVRST_N: TP319.1(TP) U1.J13(DEVRST_N)
GPIO0NB2: TP1.1(TP) U1.G14(GPIO0NB2-DDR_S_2_DQ)
GPIO0PB2: TP2.1(TP) U1.H14(GPIO0PB2-DDR_S_2_DQ)
GPIO1NB2: TP23.1(TP) U1.C14(GPIO1NB2-DDR_S_2_DQ)
GPIO1PB2: TP24.1(TP) U1.C13(GPIO1PB2-DDR_S_2_DQ)
GPIO2NB2: TP69.1(TP) U1.E13(GPIO2NB2-DDR_S_2_DQS_N)
GPIO2PB2: TP70.1(TP) U1.F13(GPIO2PB2-DDR_S_2_DQS_P)
GPIO3NB2: TP83.1(TP) U1.A14(GPIO3NB2-DDR_S_2_DQ)
GPIO3PB2: TP84.1(TP) U1.A15(GPIO3PB2-DDR_S_2_DQ)
GPIO4NB2: TP85.1(TP) U1.G13(GPIO4NB2-DDR_S_2_DQ)
GPIO4PB2: TP86.1(TP) U1.H13(GPIO4PB2-DDR_S_2_DQ)
GPIO5NB2: TP87.1(TP) U1.D14(GPIO5NB2-DDR_S_2_DQ)
GPIO5PB2: TP88.1(TP) U1.E14(GPIO5PB2-DDR_S_2_DQ)
GPIO6NB2: TP89.1(TP) U1.L21(GPIO6NB2-DDR_S_3_DQ)
GPIO6PB2: TP90.1(TP) U1.L20(GPIO6PB2-DDR_S_3_DQ-PIO_CLKIN_S)
GPIO7NB2: TP91.1(TP) U1.J18(GPIO7NB2-DDR_S_3_DQ)
GPIO7PB2: TP92.1(TP) U1.H18(GPIO7PB2-DDR_S_3_DQ-PIO_CLKIN_S)
GPIO8NB2: TP93.1(TP) U1.H17(GPIO8NB2-DDR_S_3_DQS_N)
GPIO8PB2: TP94.1(TP) U1.G17(GPIO8PB2-DDR_S_3_DQS_P-X_ANA_VR)
GPIO9NB2: TP95.1(TP) U1.K17(GPIO9NB2-DDR_S_3_DQ)
GPIO9PB2: TP96.1(TP) U1.K18(GPIO9PB2-DDR_S_3_DQ-PIO_CLKIN_S)
GPIO10NB2: TP3.1(TP) U1.K21(GPIO10NB2-DDR_S_3_DQ-LPRB_B)
GPIO10PB2: TP4.1(TP) U1.K20(GPIO10PB2-DDR_S_3_DQ-LPRB_A)
GPIO11NB2: TP5.1(TP) U1.H20(GPIO11NB2-DDR_S_3_DQ)
GPIO11PB2: TP6.1(TP) U1.J20(GPIO11PB2-DDR_S_3_DQ-PIO_CLKIN_)
GPIO12NB2: TP7.1(TP) U1.E18(GPIO12NB2-DDR_S_4_DQ)
GPIO12PB2: TP8.1(TP) U1.F18(GPIO12PB2-DDR_S_4_DQ)
GPIO13NB2: TP9.1(TP) U1.C18(GPIO13NB2-DDR_S_4_DQ)
GPIO13PB2: TP10.1(TP) U1.C17(GPIO13PB2-DDR_S_4_DQ)
GPIO14NB2: TP11.1(TP) U1.E17(GPIO14NB2-DDR_S_4_DQS_N)
GPIO14PB2: TP12.1(TP) U1.D17(GPIO14PB2-DDR_S_4_DQS_P)
GPIO15NB2: TP13.1(TP) U1.A18(GPIO15NB2-DDR_S_4_DQ)
GPIO15PB2: TP14.1(TP) U1.A17(GPIO15PB2-DDR_S_4_DQ)
GPIO16NB2: TP15.1(TP) U1.E20(GPIO16NB2-DDR_S_4_DQ)
GPIO16PB2: TP16.1(TP) U1.F20(GPIO16PB2-DDR_S_4_DQ)
GPIO17NB2: TP17.1(TP) U1.A19(GPIO17NB2-DDR_S_4_DQ)
GPIO17PB2: TP18.1(TP) U1.A20(GPIO17PB2-DDR_S_4_DQ)
GPIO18NB2: TP19.1(TP) U1.A23(GPIO18NB2-DDR_S_5_DQ)
GPIO18PB2: TP20.1(TP) U1.A22(GPIO18PB2-DDR_S_5_DQ)
GPIO19NB2: TP21.1(TP) U1.C24(GPIO19NB2-DDR_S_5_DQ)
GPIO19PB2: TP22.1(TP) U1.C23(GPIO19PB2-DDR_S_5_DQ)
GPIO20NB2: TP25.1(TP) U1.C27(GPIO20NB2-DDR_S_5_DQS_N)
GPIO20PB2: TP26.1(TP) U1.C26(GPIO20PB2-DDR_S_5_DQS_P)
GPIO21NB2: TP27.1(TP) U1.A25(GPIO21NB2-DDR_S_5_DQ)
GPIO21PB2: TP28.1(TP) U1.A24(GPIO21PB2-DDR_S_5_DQ)
GPIO22NB2: TP29.1(TP) U1.A28(GPIO22NB2-DDR_S_5_DQ)
GPIO22PB2: TP30.1(TP) U1.A27(GPIO22PB2-DDR_S_5_DQ)
GPIO23NB2: TP31.1(TP) U1.B30(GPIO23NB2-DDR_S_5_DQ)
GPIO23PB2: TP32.1(TP) U1.A29(GPIO23PB2-DDR_S_5_DQ)
GPIO24NB2: TP45.1(TP) U1.H21(GPIO24NB2-DDR_S_6_DQ)
GPIO24PB2: TP46.1(TP) U1.J21(GPIO24PB2-DDR_S_6_DQ)
GPIO25NB2: TP59.1(TP) U1.C21(GPIO25NB2-DDR_S_6_DQ)
GPIO25PB2: TP60.1(TP) U1.C20(GPIO25PB2-DDR_S_6_DQ)
GPIO26NB2: TP61.1(TP) U1.F21(GPIO26NB2-DDR_S_6_DQS_N)
GPIO26PB2: TP62.1(TP) U1.G21(GPIO26PB2-DDR_S_6_DQS_P-SE_PLL0)
GPIO27NB2: TP63.1(TP) U1.D21(GPIO27NB2-DDR_S_6_DQ)
GPIO27PB2: TP64.1(TP) U1.D20(GPIO27PB2-DDR_S_6_DQ-PIO_CLKIN_)
GPIO28NB2: TP65.1(TP) U1.F23(GPIO28NB2-DDR_S_6_DQ)
GPIO28PB2: TP66.1(TP) U1.G23(GPIO28PB2-DDR_S_6_DQ-SE_PLL0_OU)
GPIO29NB2: TP67.1(TP) U1.D23(GPIO29NB2-DDR_S_6_DQ)
GPIO29PB2: TP68.1(TP) U1.E23(GPIO29PB2-DDR_S_6_DQ-PIO_CLKIN_)
GPIO30NB2: TP71.1(TP) U1.E24(GPIO30NB2-DDR_S_7_DQ)
GPIO30PB2: TP72.1(TP) U1.D26(GPIO30PB2-DDR_S_7_DQ)
GPIO31NB2: TP73.1(TP) U1.G25(GPIO31NB2-DDR_S_7_DQ)
GPIO31PB2: TP74.1(TP) U1.F24(GPIO31PB2-DDR_S_7_DQ)
GPIO32NB2: TP75.1(TP) U1.E27(GPIO32NB2-DDR_S_7_DQS_N)
GPIO32PB2: TP76.1(TP) U1.E28(GPIO32PB2-DDR_S_7_DQS_P-SE_PLL1)
GPIO33NB2: TP77.1(TP) U1.G26(GPIO33NB2-DDR_S_7_DQ)
GPIO33PB2: TP78.1(TP) U1.H25(GPIO33PB2-DDR_S_7_DQ-PIO_CLKIN_)
GPIO34NB2: TP79.1(TP) U1.D28(GPIO34NB2-DDR_S_7_DQ)
GPIO34PB2: TP80.1(TP) U1.C28(GPIO34PB2-DDR_S_7_DQ-SE_PLL1_OU)
GPIO35NB2: TP81.1(TP) U1.G28(GPIO35NB2-DDR_S_7_DQ-SE_DTEST_O)
GPIO35PB2: TP82.1(TP) U1.G27(GPIO35PB2-DDR_S_7_DQ-PIO_CLKIN_)
GPIO174NB4: TP97.1(TP) U1.AC4(GPIO174NB4-DDR_W_11_DQ)
GPIO174PB4: TP98.1(TP) U1.AD3(GPIO174PB4-DDR_W_11_DQ-PIO_CLKI)
GPIO175NB4: TP99.1(TP) U1.AD1(GPIO175NB4-DDR_W_11_DQS_N)
GPIO175PB4: TP100.1(TP) U1.AC1(GPIO175PB4-DDR_W_11_DQS_P-NW_AT)
GPIO176NB4: TP101.1(TP) U1.AB1(GPIO176NB4-DDR_W_11_DQ)
GPIO176PB4: TP102.1(TP) U1.AA1(GPIO176PB4-DDR_W_11_DQ)
GPIO177NB4: TP103.1(TP) U1.AC6(GPIO177NB4-DDR_W_11_DQ)
GPIO177PB4: TP104.1(TP) U1.AC5(GPIO177PB4-DDR_W_11_DQ)
GPIO178NB4: TP105.1(TP) U1.Y6(GPIO178NB4-DDR_W_10_DQ)
GPIO178PB4: TP106.1(TP) U1.Y5(GPIO178PB4-DDR_W_10_DQ)
GPIO179NB4: TP107.1(TP) U1.AA7(GPIO179NB4-DDR_W_10_DQ)
GPIO179PB4: TP108.1(TP) U1.AA6(GPIO179PB4-DDR_W_10_DQ)
GPIO180NB4: TP109.1(TP) U1.Y4(GPIO180NB4-DDR_W_10_DQ)
GPIO180PB4: TP110.1(TP) U1.Y3(GPIO180PB4-DDR_W_10_DQ-PIO_CLKI)
GPIO181NB4: TP111.1(TP) U1.Y8(GPIO181NB4-DDR_W_10_DQS_N)
GPIO181PB4: TP112.1(TP) U1.AA8(GPIO181PB4-DDR_W_10_DQS_P-NW_PL)
GPIO182NB4: TP113.1(TP) U1.AA3(GPIO182NB4-DDR_W_10_DQ)
GPIO182PB4: TP114.1(TP) U1.AA4(GPIO182PB4-DDR_W_10_DQ)
GPIO183NB4: TP115.1(TP) U1.V10(GPIO183NB4-DDR_W_10_DQ)
GPIO183PB4: TP116.1(TP) U1.V9(GPIO183PB4-DDR_W_10_DQ)
GPIO184NB4: TP117.1(TP) U1.V5(GPIO184NB4-DDR_W_9_DQ)
GPIO184PB4: TP118.1(TP) U1.U5(GPIO184PB4-DDR_W_9_DQ)
GPIO185NB4: TP119.1(TP) U1.V3(GPIO185NB4-DDR_W_9_DQ)
GPIO185PB4: TP120.1(TP) U1.U4(GPIO185PB4-DDR_W_9_DQ)
GPIO186NB4: TP121.1(TP) U1.U9(GPIO186NB4-DDR_W_9_DQ)
GPIO186PB4: TP122.1(TP) U1.U8(GPIO186PB4-DDR_W_9_DQ)
GPIO187NB4: TP123.1(TP) U1.W1(GPIO187NB4-DDR_W_9_DQS_N)
GPIO187PB4: TP124.1(TP) U1.V1(GPIO187PB4-DDR_W_9_DQS_P)
GPIO188NB4: TP125.1(TP) U1.U7(GPIO188NB4-DDR_W_9_DQ)
GPIO188PB4: TP126.1(TP) U1.V6(GPIO188PB4-DDR_W_9_DQ)
GPIO189NB4: TP127.1(TP) U1.V8(GPIO189NB4-DDR_W_9_DQ)
GPIO189PB4: TP128.1(TP) U1.V7(GPIO189PB4-DDR_W_9_DQ)
GPIO198NB4: TP129.1(TP) U1.U3(GPIO198NB4-DDR_W_7_DQ)
GPIO198PB4: TP130.1(TP) U1.P3(GPIO198PB4-DDR_W_7_DQ)
GPIO199NB4: TP131.1(TP) U1.U1(GPIO199NB4-DDR_W_7_DQS_N)
GPIO199PB4: TP132.1(TP) U1.T1(GPIO199PB4-DDR_W_7_DQS_P)
GPIO202NB4: TP145.1(TP) U1.P5(GPIO202NB4-DDR_W_6_DQ)
GPIO202PB4: TP146.1(TP) U1.N5(GPIO202PB4-DDR_W_6_DQ)
GPIO203NB4: TP147.1(TP) U1.P4(GPIO203NB4-DDR_W_6_DQ)
GPIO203PB4: TP148.1(TP) U1.N3(GPIO203PB4-DDR_W_6_DQ)
GPIO204NB4: TP149.1(TP) U1.P9(GPIO204NB4-DDR_W_6_DQ)
GPIO204PB4: TP150.1(TP) U1.P8(GPIO204PB4-DDR_W_6_DQ)
GPIO205NB4: TP151.1(TP) U1.P1(GPIO205NB4-DDR_W_6_DQS_N)
GPIO205PB4: TP152.1(TP) U1.N1(GPIO205PB4-DDR_W_6_DQS_P)
GPIO206NB4: TP153.1(TP) U1.M1(GPIO206NB4-DDR_W_6_DQ)
GPIO206PB4: TP154.1(TP) U1.L1(GPIO206PB4-DDR_W_6_DQ)
GPIO207NB4: TP155.1(TP) U1.P7(GPIO207NB4-DDR_W_6_DQ)
GPIO207PB4: TP156.1(TP) U1.N6(GPIO207PB4-DDR_W_6_DQ)
GPIO208NB4: TP157.1(TP) U1.K4(GPIO208NB4-DDR_W_5_DQ)
GPIO208PB4: TP158.1(TP) U1.K3(GPIO208PB4-DDR_W_5_DQ)
GPIO209NB4: TP159.1(TP) U1.N9(GPIO209NB4-DDR_W_5_DQ)
GPIO209PB4: TP160.1(TP) U1.N10(GPIO209PB4-DDR_W_5_DQ)
GPIO210NB4: TP161.1(TP) U1.L5(GPIO210NB4-DDR_W_5_DQ)
GPIO210PB4: TP162.1(TP) U1.L6(GPIO210PB4-DDR_W_5_DQ)
GPIO211NB4: TP163.1(TP) U1.N7(GPIO211NB4-DDR_W_5_DQS_N)
GPIO211PB4: TP164.1(TP) U1.N8(GPIO211PB4-DDR_W_5_DQS_P)
GPIO212NB4: TP165.1(TP) U1.L4(GPIO212NB4-DDR_W_5_DQ)
GPIO212PB4: TP166.1(TP) U1.L3(GPIO212PB4-DDR_W_5_DQ)
GPIO213NB4: TP167.1(TP) U1.K7(GPIO213NB4-DDR_W_5_DQ)
GPIO213PB4: TP168.1(TP) U1.K6(GPIO213PB4-DDR_W_5_DQ)
GPIO214NB4: TP169.1(TP) U1.J1(GPIO214NB4-DDR_W_4_DQ)
GPIO214PB4: TP170.1(TP) U1.H1(GPIO214PB4-DDR_W_4_DQ)
GPIO215NB4: TP171.1(TP) U1.G4(GPIO215NB4-DDR_W_4_DQ)
GPIO215PB4: TP172.1(TP) U1.G3(GPIO215PB4-DDR_W_4_DQ-PIO_CLKIN)
GPIO216NB4: TP173.1(TP) U1.H5(GPIO216NB4-DDR_W_4_DQ)
GPIO216PB4: TP174.1(TP) U1.H4(GPIO216PB4-DDR_W_4_DQ-PIO_CLKIN)
GPIO217NB4: TP175.1(TP) U1.G1(GPIO217NB4-DDR_W_4_DQS_N)
GPIO217PB4: TP176.1(TP) U1.F1(GPIO217PB4-DDR_W_4_DQS_P)
GPIO218NB4: TP177.1(TP) U1.E4(GPIO218NB4-DDR_W_4_DQ)
GPIO218PB4: TP178.1(TP) U1.E3(GPIO218PB4-DDR_W_4_DQ)
GPIO219NB4: TP179.1(TP) U1.H6(GPIO219NB4-DDR_W_4_DQ)
GPIO219PB4: TP180.1(TP) U1.G5(GPIO219PB4-DDR_W_4_DQ-PIO_CLKIN)
GPIO238NB5: TP181.1(TP) U1.C1(GPIO238NB5-DDR_W_0_DQ)
GPIO238PB5: TP182.1(TP) U1.B1(GPIO238PB5-DDR_W_0_DQ-SW_PLL0_O)
GPIO239NB5: TP183.1(TP) U1.D1(GPIO239NB5-DDR_W_0_DQ)
GPIO239PB5: TP184.1(TP) U1.D3(GPIO239PB5-DDR_W_0_DQ-PIO_CLKIN)
GPIO240NB5: TP185.1(TP) U1.C5(GPIO240NB5-DDR_W_0_DQ)
GPIO240PB5: TP186.1(TP) U1.D5(GPIO240PB5-DDR_W_0_DQ-PIO_CLKIN)
GPIO241NB5: TP187.1(TP) U1.A2(GPIO241NB5-DDR_W_0_DQS_N)
GPIO241PB5: TP188.1(TP) U1.A3(GPIO241PB5-DDR_W_0_DQS_P-SW_PLL)
GPIO242NB5: TP189.1(TP) U1.A4(GPIO242NB5-DDR_W_0_DQ)
GPIO242PB5: TP190.1(TP) U1.A5(GPIO242PB5-DDR_W_0_DQ-SW_ATEST_)
GPIO243NB5: TP191.1(TP) U1.C4(GPIO243NB5-DDR_W_0_DQ)
GPIO243PB5: TP192.1(TP) U1.C3(GPIO243PB5-DDR_W_0_DQ-PIO_CLKIN)
GPIO244NB2: TP33.1(TP) U1.H7(GPIO244NB2-DDR_S_0_DQ-SW_DTEST_)
GPIO244PB2: TP34.1(TP) U1.G6(GPIO244PB2-DDR_S_0_DQ-PIO_CLKIN)
GPIO245NB2: TP35.1(TP) U1.D8(GPIO245NB2-DDR_S_0_DQ)
GPIO245PB2: TP36.1(TP) U1.E8(GPIO245PB2-DDR_S_0_DQ-PIO_CLKIN)
GPIO246NB2: TP37.1(TP) U1.E7(GPIO246NB2-DDR_S_0_DQS_N)
GPIO246PB2: TP38.1(TP) U1.F7(GPIO246PB2-DDR_S_0_DQS_P-SW_PLL)
GPIO247NB2: TP39.1(TP) U1.G8(GPIO247NB2-DDR_S_0_DQ)
GPIO247PB2: TP40.1(TP) U1.F8(GPIO247PB2-DDR_S_0_DQ-PIO_CLKIN)
GPIO248NB2: TP41.1(TP) U1.A8(GPIO248NB2-DDR_S_0_DQ)
GPIO248PB2: TP42.1(TP) U1.A7(GPIO248PB2-DDR_S_0_DQ-SW_PLL1_O)
GPIO249NB2: TP43.1(TP) U1.C7(GPIO249NB2-DDR_S_0_DQ)
GPIO249PB2: TP44.1(TP) U1.D7(GPIO249PB2-DDR_S_0_DQ-PIO_CLKIN)
GPIO250NB2: TP47.1(TP) U1.D10(GPIO250NB2-DDR_S_1_DQ)
GPIO250PB2: TP48.1(TP) U1.C10(GPIO250PB2-DDR_S_1_DQ)
GPIO251NB2: TP49.1(TP) U1.A9(GPIO251NB2-DDR_S_1_DQ)
GPIO251PB2: TP50.1(TP) U1.A10(GPIO251PB2-DDR_S_1_DQ)
GPIO252NB2: TP51.1(TP) U1.E11(GPIO252NB2-DDR_S_1_DQS_N)
GPIO252PB2: TP52.1(TP) U1.F11(GPIO252PB2-DDR_S_1_DQS_P)
GPIO253NB2: TP53.1(TP) U1.D11(GPIO253NB2-DDR_S_1_DQ)
GPIO253PB2: TP54.1(TP) U1.C11(GPIO253PB2-DDR_S_1_DQ)
GPIO254NB2: TP55.1(TP) U1.G10(GPIO254NB2-DDR_S_1_DQ)
GPIO254PB2: TP56.1(TP) U1.F10(GPIO254PB2-DDR_S_1_DQ)
GPIO255NB2: TP57.1(TP) U1.A13(GPIO255NB2-DDR_S_1_DQ)
GPIO255PB2: TP58.1(TP) U1.A12(GPIO255PB2-DDR_S_1_DQ)
HSIO72NB1: TP258.1(TP) U1.AJ30(HSIO72NB1-DDR_N_16_DQ-NE_DTEST_)
HSIO72PB1: TP259.1(TP) U1.AK29(HSIO72PB1-DDR_N_16_DQ-PIO_CLKIN)
HSIO73NB1: TP260.1(TP) U1.AF28(HSIO73NB1-DDR_N_16_DQ)
HSIO73PB1: TP261.1(TP) U1.AG28(HSIO73PB1-DDR_N_16_DQ-NE_PLL0_O)
HSIO74NB1: TP262.1(TP) U1.AH26(HSIO74NB1-DDR_N_16_DQ)
HSIO74PB1: TP263.1(TP) U1.AG26(HSIO74PB1-DDR_N_16_DQ-PIO_CLKIN)
HSIO75NB1: TP264.1(TP) U1.AK28(HSIO75NB1-DDR_N_16_DQS_N)
HSIO75PB1: TP265.1(TP) U1.AK27(HSIO75PB1-DDR_N_16_DQS_P-NE_PLL)
HSIO76NB1: TP266.1(TP) U1.AH28(HSIO76NB1-DDR_N_16_DQ)
HSIO76PB1: TP267.1(TP) U1.AH27(HSIO76PB1-DDR_N_16_DQ)
HSIO77NB1: TP268.1(TP) U1.AD28(HSIO77NB1-DDR_N_16_DQ)
HSIO77PB1: TP269.1(TP) U1.AD27(HSIO77PB1-DDR_N_16_DQ)
HSIO78NB1: TP270.1(TP) U1.AD25(HSIO78NB1-DDR_N_15_DQ)
HSIO78PB1: TP271.1(TP) U1.AE24(HSIO78PB1-DDR_N_15_DQ-PIO_CLKIN)
HSIO79NB1: TP272.1(TP) U1.AC25(HSIO79NB1-DDR_N_15_DQ)
HSIO79PB1: TP273.1(TP) U1.AD26(HSIO79PB1-DDR_N_15_DQ-NE_PLL1_O)
HSIO80NB1: TP274.1(TP) U1.AF24(HSIO80NB1-DDR_N_15_DQ)
HSIO80PB1: TP275.1(TP) U1.AG23(HSIO80PB1-DDR_N_15_DQ-PIO_CLKIN)
HSIO81NB1: TP276.1(TP) U1.AE23(HSIO81NB1-DDR_N_15_DQS_N)
HSIO81PB1: TP277.1(TP) U1.AF23(HSIO81PB1-DDR_N_15_DQS_P-NE_PLL)
HSIO82NB1: TP278.1(TP) U1.AH23(HSIO82NB1-DDR_N_15_DQ)
HSIO82PB1: TP279.1(TP) U1.AH24(HSIO82PB1-DDR_N_15_DQ)
HSIO83NB1: TP280.1(TP) U1.AD23(HSIO83NB1-DDR_N_15_DQ)
HSIO83PB1: TP281.1(TP) U1.AB21(HSIO83PB1-DDR_N_15_DQ)
HSIO84NB1: TP282.1(TP) U1.AK25(HSIO84NB1-DDR_N_14_DQ)
HSIO84PB1: TP283.1(TP) U1.AK24(HSIO84PB1-DDR_N_14_DQ)
HSIO85NB1: TP284.1(TP) U1.AG21(HSIO85NB1-DDR_N_14_DQ)
HSIO85PB1: TP285.1(TP) U1.AH21(HSIO85PB1-DDR_N_14_DQ)
HSIO86NB1: TP286.1(TP) U1.AE21(HSIO86NB1-DDR_N_14_DQ)
HSIO86PB1: TP287.1(TP) U1.AE20(HSIO86PB1-DDR_N_14_DQ)
HSIO87NB1: TP288.1(TP) U1.AK23(HSIO87NB1-DDR_N_14_DQS_N)
HSIO87PB1: TP289.1(TP) U1.AK22(HSIO87PB1-DDR_N_14_DQS_P)
HSIO88NB1: TP290.1(TP) U1.AF20(HSIO88NB1-DDR_N_14_DQ)
HSIO88PB1: TP291.1(TP) U1.AG20(HSIO88PB1-DDR_N_14_DQ)
HSIO89NB1: TP292.1(TP) U1.AC21(HSIO89NB1-DDR_N_14_DQ)
HSIO89PB1: TP293.1(TP) U1.AD21(HSIO89PB1-DDR_N_14_DQ)
HSIO90NB1: TP294.1(TP) U1.AK20(HSIO90NB1-DDR_N_13_DQ)
HSIO90PB1: TP295.1(TP) U1.AK19(HSIO90PB1-DDR_N_13_DQ)
HSIO91NB1: TP296.1(TP) U1.AH20(HSIO91NB1-DDR_N_13_DQ)
HSIO91PB1: TP297.1(TP) U1.AH18(HSIO91PB1-DDR_N_13_DQ)
HSIO92NB1: TP298.1(TP) U1.AK18(HSIO92NB1-DDR_N_13_DQ)
HSIO92PB1: TP299.1(TP) U1.AK17(HSIO92PB1-DDR_N_13_DQ)
HSIO93NB1: TP300.1(TP) U1.AE18(HSIO93NB1-DDR_N_13_DQS_N)
HSIO93PB1: TP301.1(TP) U1.AF18(HSIO93PB1-DDR_N_13_DQS_P)
HSIO94NB1: TP302.1(TP) U1.AH17(HSIO94NB1-DDR_N_13_DQ)
HSIO94PB1: TP303.1(TP) U1.AK15(HSIO94PB1-DDR_N_13_DQ)
HSIO95NB1: TP304.1(TP) U1.AF17(HSIO95NB1-DDR_N_13_DQ)
HSIO95PB1: TP305.1(TP) U1.AG17(HSIO95PB1-DDR_N_13_DQ)
HSIO96NB1: TP306.1(TP) U1.AD18(HSIO96NB1-DDR_N_12_DQ)
HSIO96PB1: TP307.1(TP) U1.AC18(HSIO96PB1-DDR_N_12_DQ-PIO_CLKIN)
HSIO97NB1: TP308.1(TP) U1.AB18(HSIO97NB1-DDR_N_12_DQ)
HSIO97PB1: TP309.1(TP) U1.AA18(HSIO97PB1-DDR_N_12_DQ)
HSIO98NB1: TP310.1(TP) U1.AA21(HSIO98NB1-DDR_N_12_DQ)
HSIO98PB1: TP311.1(TP) U1.AA20(HSIO98PB1-DDR_N_12_DQ-PIO_CLKIN)
HSIO99NB1: TP312.1(TP) U1.AD17(HSIO99NB1-DDR_N_12_DQS_N)
HSIO99PB1: TP313.1(TP) U1.AC17(HSIO99PB1-DDR_N_12_DQS_P)
HSIO100NB1: TP254.1(TP) U1.AA17(HSIO100NB1-DDR_N_12_DQ)
HSIO100PB1: TP255.1(TP) U1.Y17(HSIO100PB1-DDR_N_12_DQ)
HSIO101NB1: TP256.1(TP) U1.AC20(HSIO101NB1-DDR_N_12_DQ)
HSIO101PB1: TP257.1(TP) U1.AB20(HSIO101PB1-DDR_N_12_DQ)
HSIO144NB0: TP193.1(TP) U1.AH13(HSIO144NB0-DDR_N_4_DQ)
HSIO144PB0: TP194.1(TP) U1.AK14(HSIO144PB0-DDR_N_4_DQ-PIO_CLKIN)
HSIO145NB0: TP195.1(TP) U1.AH14(HSIO145NB0-DDR_N_4_DQ)
HSIO145PB0: TP196.1(TP) U1.AG14(HSIO145PB0-DDR_N_4_DQ)
HSIO146NB0: TP197.1(TP) U1.AE13(HSIO146NB0-DDR_N_4_DQ)
HSIO146PB0: TP198.1(TP) U1.AD13(HSIO146PB0-DDR_N_4_DQ-PIO_CLKIN)
HSIO147NB0: TP199.1(TP) U1.AK13(HSIO147NB0-DDR_N_4_DQS_N)
HSIO147PB0: TP200.1(TP) U1.AK12(HSIO147PB0-DDR_N_4_DQS_P)
HSIO148NB0: TP201.1(TP) U1.AF14(HSIO148NB0-DDR_N_4_DQ)
HSIO148PB0: TP202.1(TP) U1.AF13(HSIO148PB0-DDR_N_4_DQ)
HSIO149NB0: TP203.1(TP) U1.AD14(HSIO149NB0-DDR_N_4_DQ)
HSIO149PB0: TP204.1(TP) U1.AC14(HSIO149PB0-DDR_N_4_DQ)
HSIO150NB0: TP205.1(TP) U1.AG10(HSIO150NB0-DDR_N_3_DQ)
HSIO150PB0: TP206.1(TP) U1.AH10(HSIO150PB0-DDR_N_3_DQ)
HSIO151NB0: TP207.1(TP) U1.AF11(HSIO151NB0-DDR_N_3_DQ)
HSIO151PB0: TP208.1(TP) U1.AE11(HSIO151PB0-DDR_N_3_DQ)
HSIO152NB0: TP209.1(TP) U1.AH11(HSIO152NB0-DDR_N_3_DQ)
HSIO152PB0: TP210.1(TP) U1.AG11(HSIO152PB0-DDR_N_3_DQ)
HSIO153NB0: TP211.1(TP) U1.AE10(HSIO153NB0-DDR_N_3_DQS_N)
HSIO153PB0: TP212.1(TP) U1.AF8(HSIO153PB0-DDR_N_3_DQS_P)
HSIO154NB0: TP213.1(TP) U1.AK10(HSIO154NB0-DDR_N_3_DQ)
HSIO154PB0: TP214.1(TP) U1.AK9(HSIO154PB0-DDR_N_3_DQ)
HSIO155NB0: TP215.1(TP) U1.AE8(HSIO155NB0-DDR_N_3_DQ)
HSIO155PB0: TP216.1(TP) U1.AD8(HSIO155PB0-DDR_N_3_DQ)
HSIO156NB0: TP217.1(TP) U1.AA13(HSIO156NB0-DDR_N_2_DQ)
HSIO156PB0: TP218.1(TP) U1.AB13(HSIO156PB0-DDR_N_2_DQ)
HSIO157NB0: TP219.1(TP) U1.AC13(HSIO157NB0-DDR_N_2_DQ)
HSIO157PB0: TP220.1(TP) U1.AC11(HSIO157PB0-DDR_N_2_DQ)
HSIO158NB0: TP221.1(TP) U1.AA11(HSIO158NB0-DDR_N_2_DQ)
HSIO158PB0: TP222.1(TP) U1.Y11(HSIO158PB0-DDR_N_2_DQ)
HSIO159NB0: TP224.1(TP) U1.AD10(HSIO159NB0-DDR_N_2_DQS_N)
HSIO159PB0: TP225.1(TP) U1.AC10(HSIO159PB0-DDR_N_2_DQS_P)
HSIO160NB0: TP226.1(TP) U1.AB11(HSIO160NB0-DDR_N_2_DQ)
HSIO160PB0: TP227.1(TP) U1.AB10(HSIO160PB0-DDR_N_2_DQ)
HSIO161NB0: TP228.1(TP) U1.AA14(HSIO161NB0-DDR_N_2_DQ)
HSIO161PB0: TP229.1(TP) U1.Y14(HSIO161PB0-DDR_N_2_DQ)
HSIO162NB0: TP230.1(TP) U1.AK7(HSIO162NB0-DDR_N_1_DQ)
HSIO162PB0: TP231.1(TP) U1.AK8(HSIO162PB0-DDR_N_1_DQ)
HSIO163NB0: TP232.1(TP) U1.AF7(HSIO163NB0-DDR_N_1_DQ)
HSIO163PB0: TP233.1(TP) U1.AE7(HSIO163PB0-DDR_N_1_DQ)
HSIO164NB0: TP234.1(TP) U1.AK5(HSIO164NB0-DDR_N_1_DQ)
HSIO164PB0: TP235.1(TP) U1.AK4(HSIO164PB0-DDR_N_1_DQ)
HSIO165NB0: TP236.1(TP) U1.AH7(HSIO165NB0-DDR_N_1_DQS_N)
HSIO165PB0: TP237.1(TP) U1.AG8(HSIO165PB0-DDR_N_1_DQS_P)
HSIO166NB0: TP238.1(TP) U1.AH5(HSIO166NB0-DDR_N_1_DQ)
HSIO166PB0: TP239.1(TP) U1.AH4(HSIO166PB0-DDR_N_1_DQ)
HSIO167NB0: TP240.1(TP) U1.AG7(HSIO167NB0-DDR_N_1_DQ)
HSIO167PB0: TP241.1(TP) U1.AG5(HSIO167PB0-DDR_N_1_DQ)
HSIO168NB0: TP242.1(TP) U1.AK3(HSIO168NB0-DDR_N_0_DQ)
HSIO168PB0: TP243.1(TP) U1.AK2(HSIO168PB0-DDR_N_0_DQ-PIO_CLKIN)
HSIO169NB0: TP244.1(TP) U1.AJ1(HSIO169NB0-DDR_N_0_DQ)
HSIO169PB0: TP245.1(TP) U1.AH1(HSIO169PB0-DDR_N_0_DQ-NW_PLL1_O)
HSIO170NB0: TP246.1(TP) U1.AD6(HSIO170NB0-DDR_N_0_DQ)
HSIO170PB0: TP247.1(TP) U1.AD5(HSIO170PB0-DDR_N_0_DQ-PIO_CLKIN)
HSIO171NB0: TP248.1(TP) U1.AH3(HSIO171NB0-DDR_N_0_DQS_N)
